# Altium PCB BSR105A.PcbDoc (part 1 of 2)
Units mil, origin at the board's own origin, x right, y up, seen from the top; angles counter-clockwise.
Board outline 4010.03 x 4016.63 mil, 6 copper layers (Top Layer, Mid-Layer 1, Mid-Layer 2, Mid-Layer 3, Mid-Layer 4, Bottom Layer), stack 61.2 mil thick; 166 components, 58 nets, 398 pads, 190 vias.
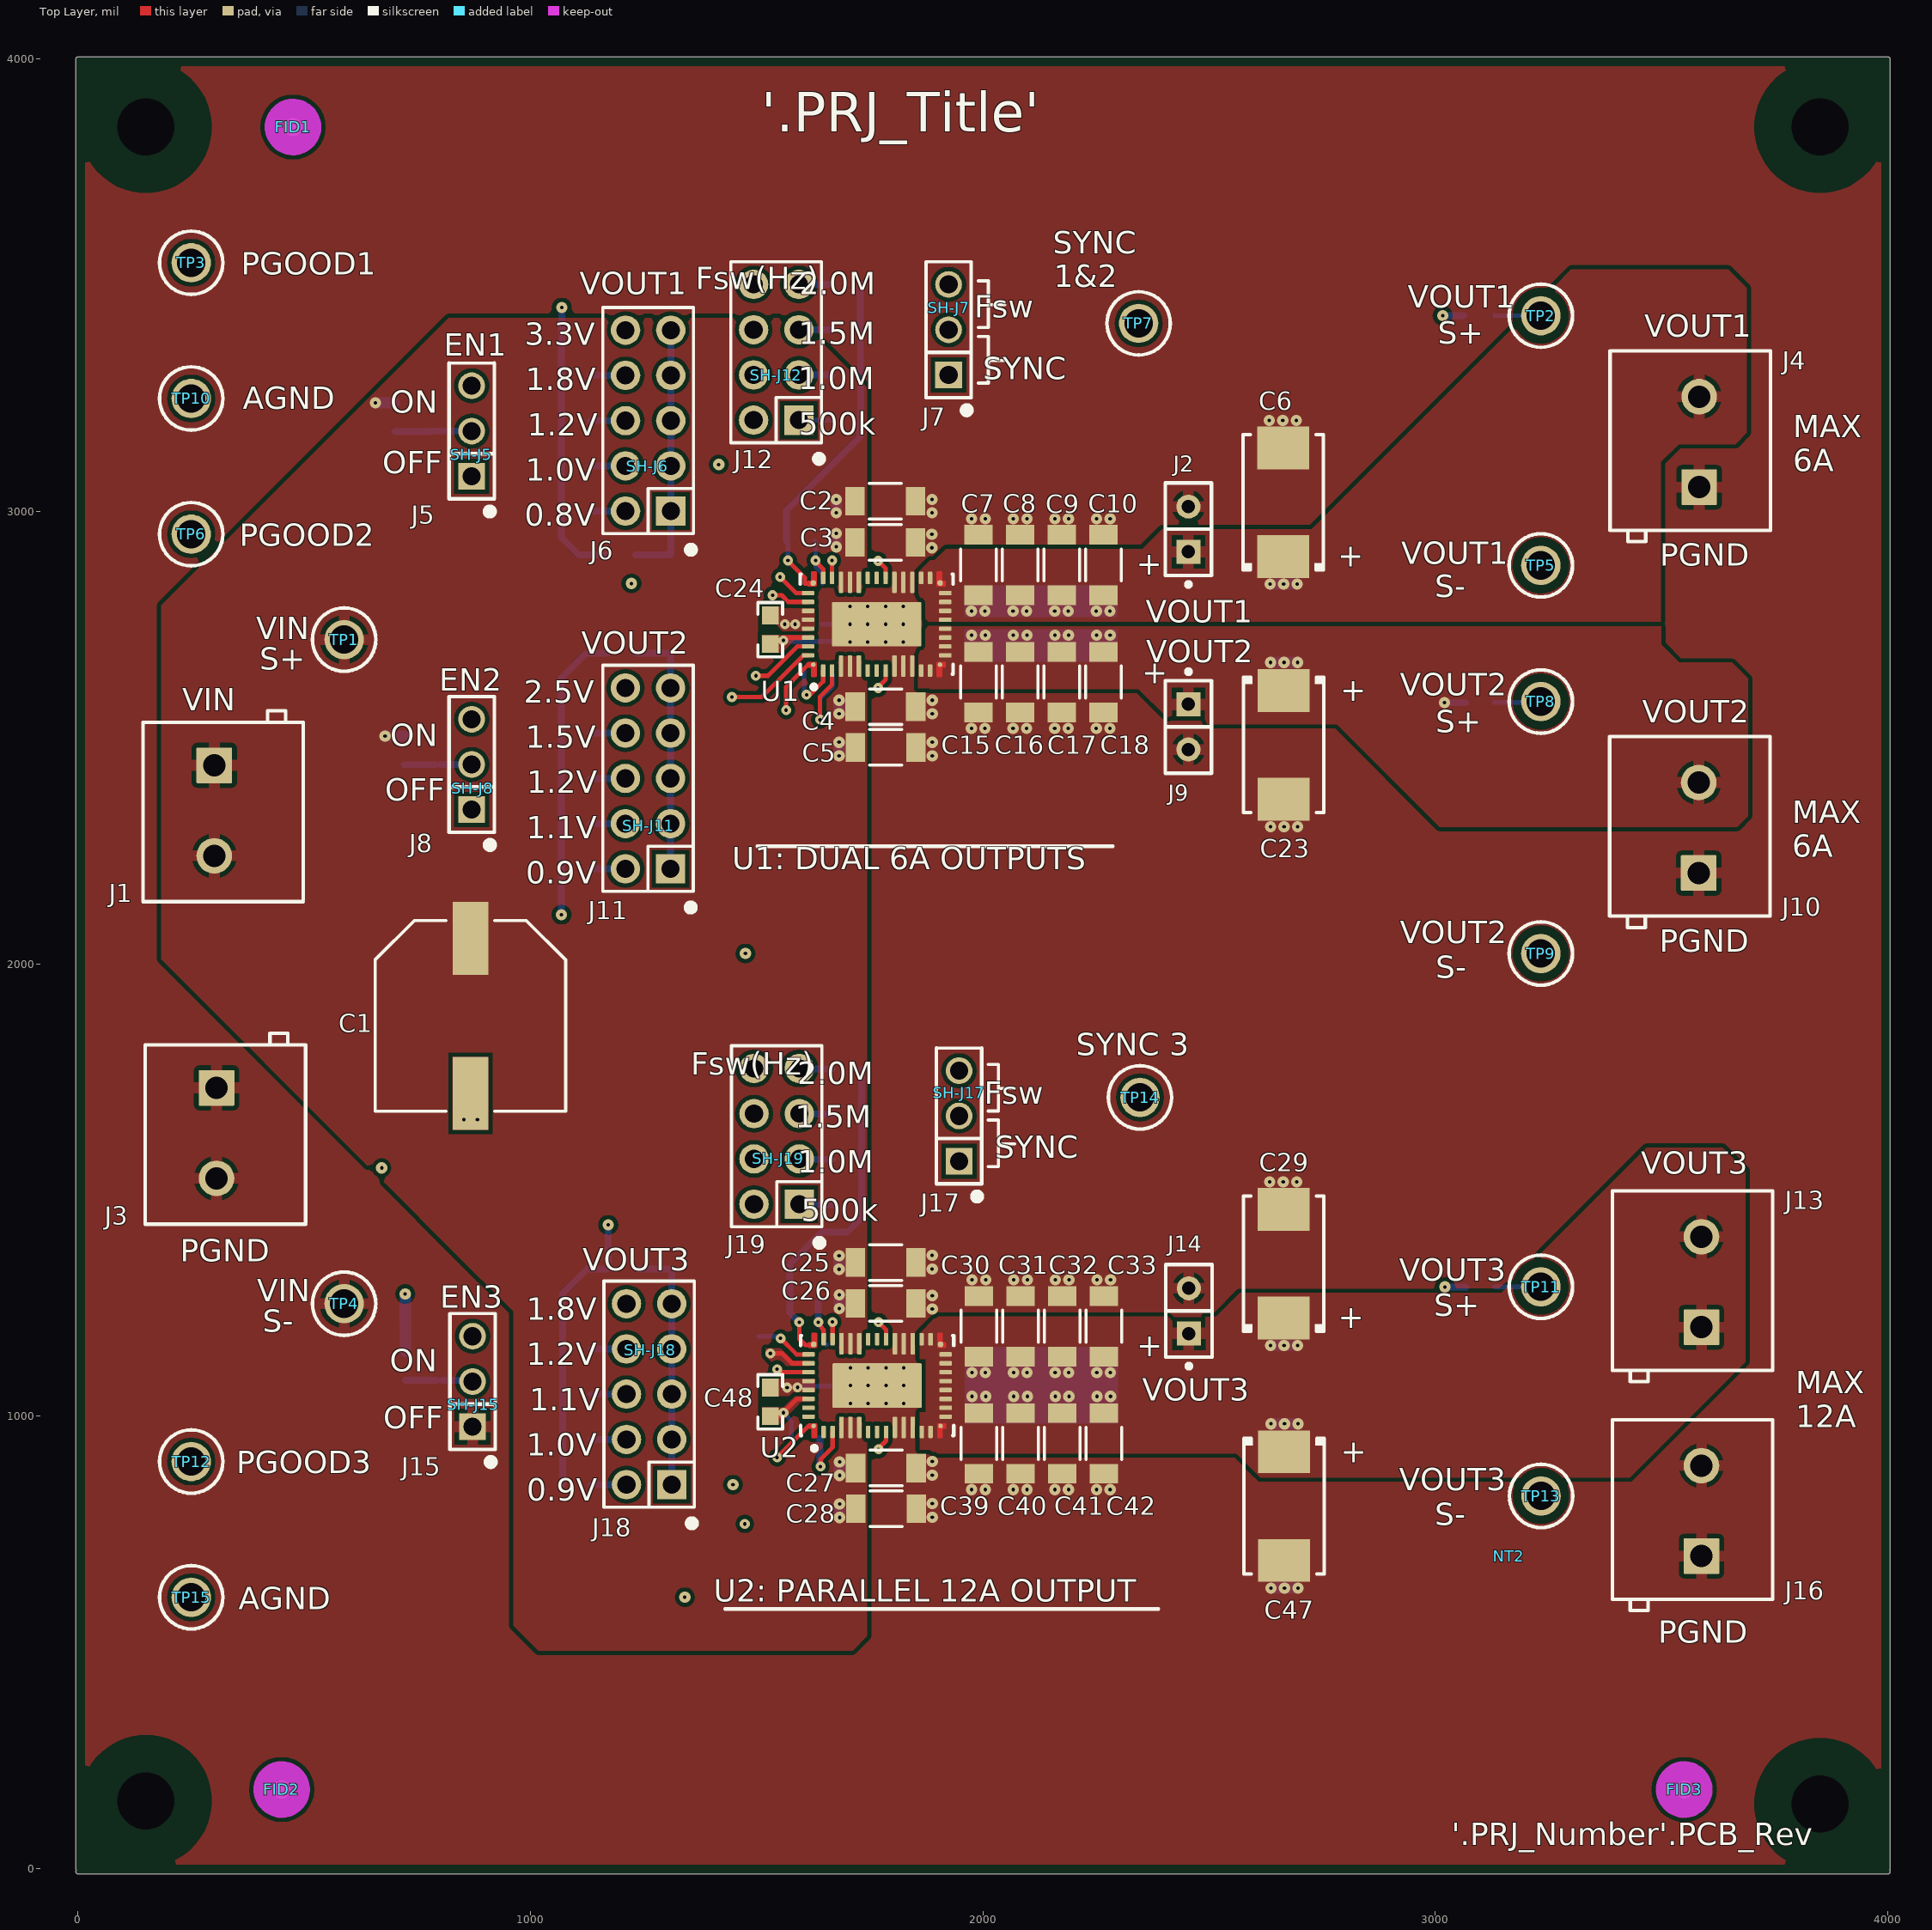
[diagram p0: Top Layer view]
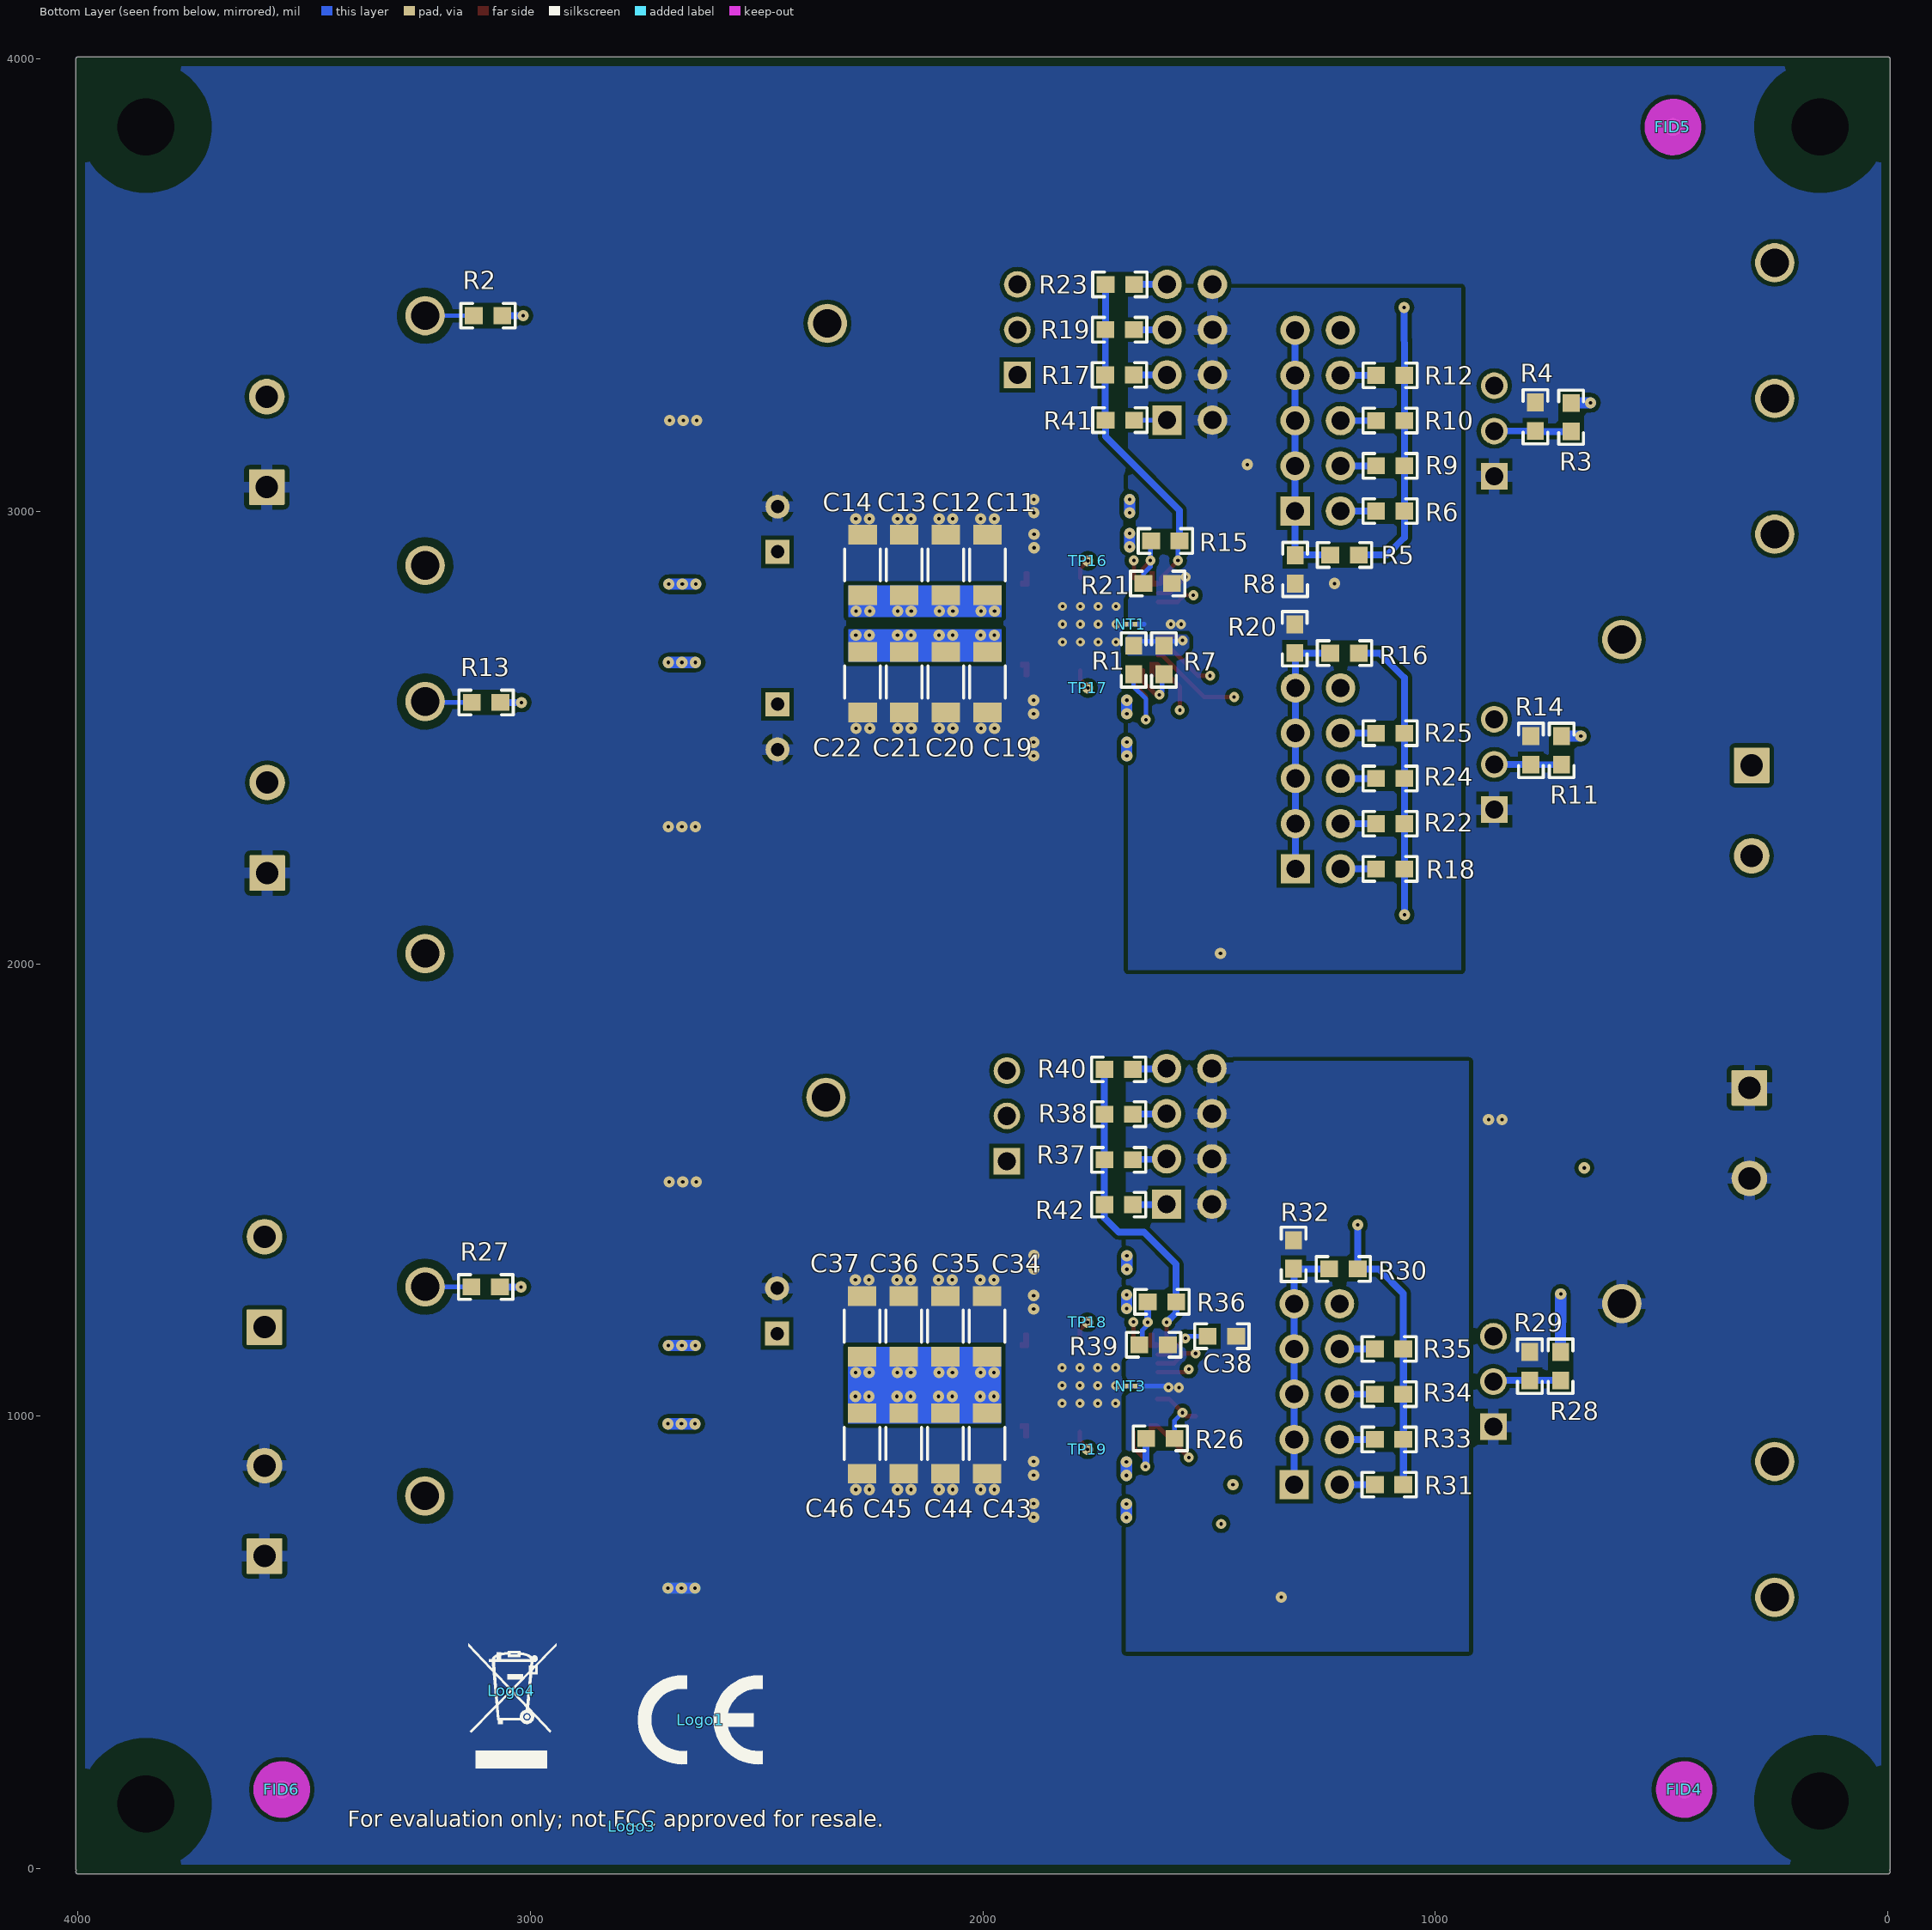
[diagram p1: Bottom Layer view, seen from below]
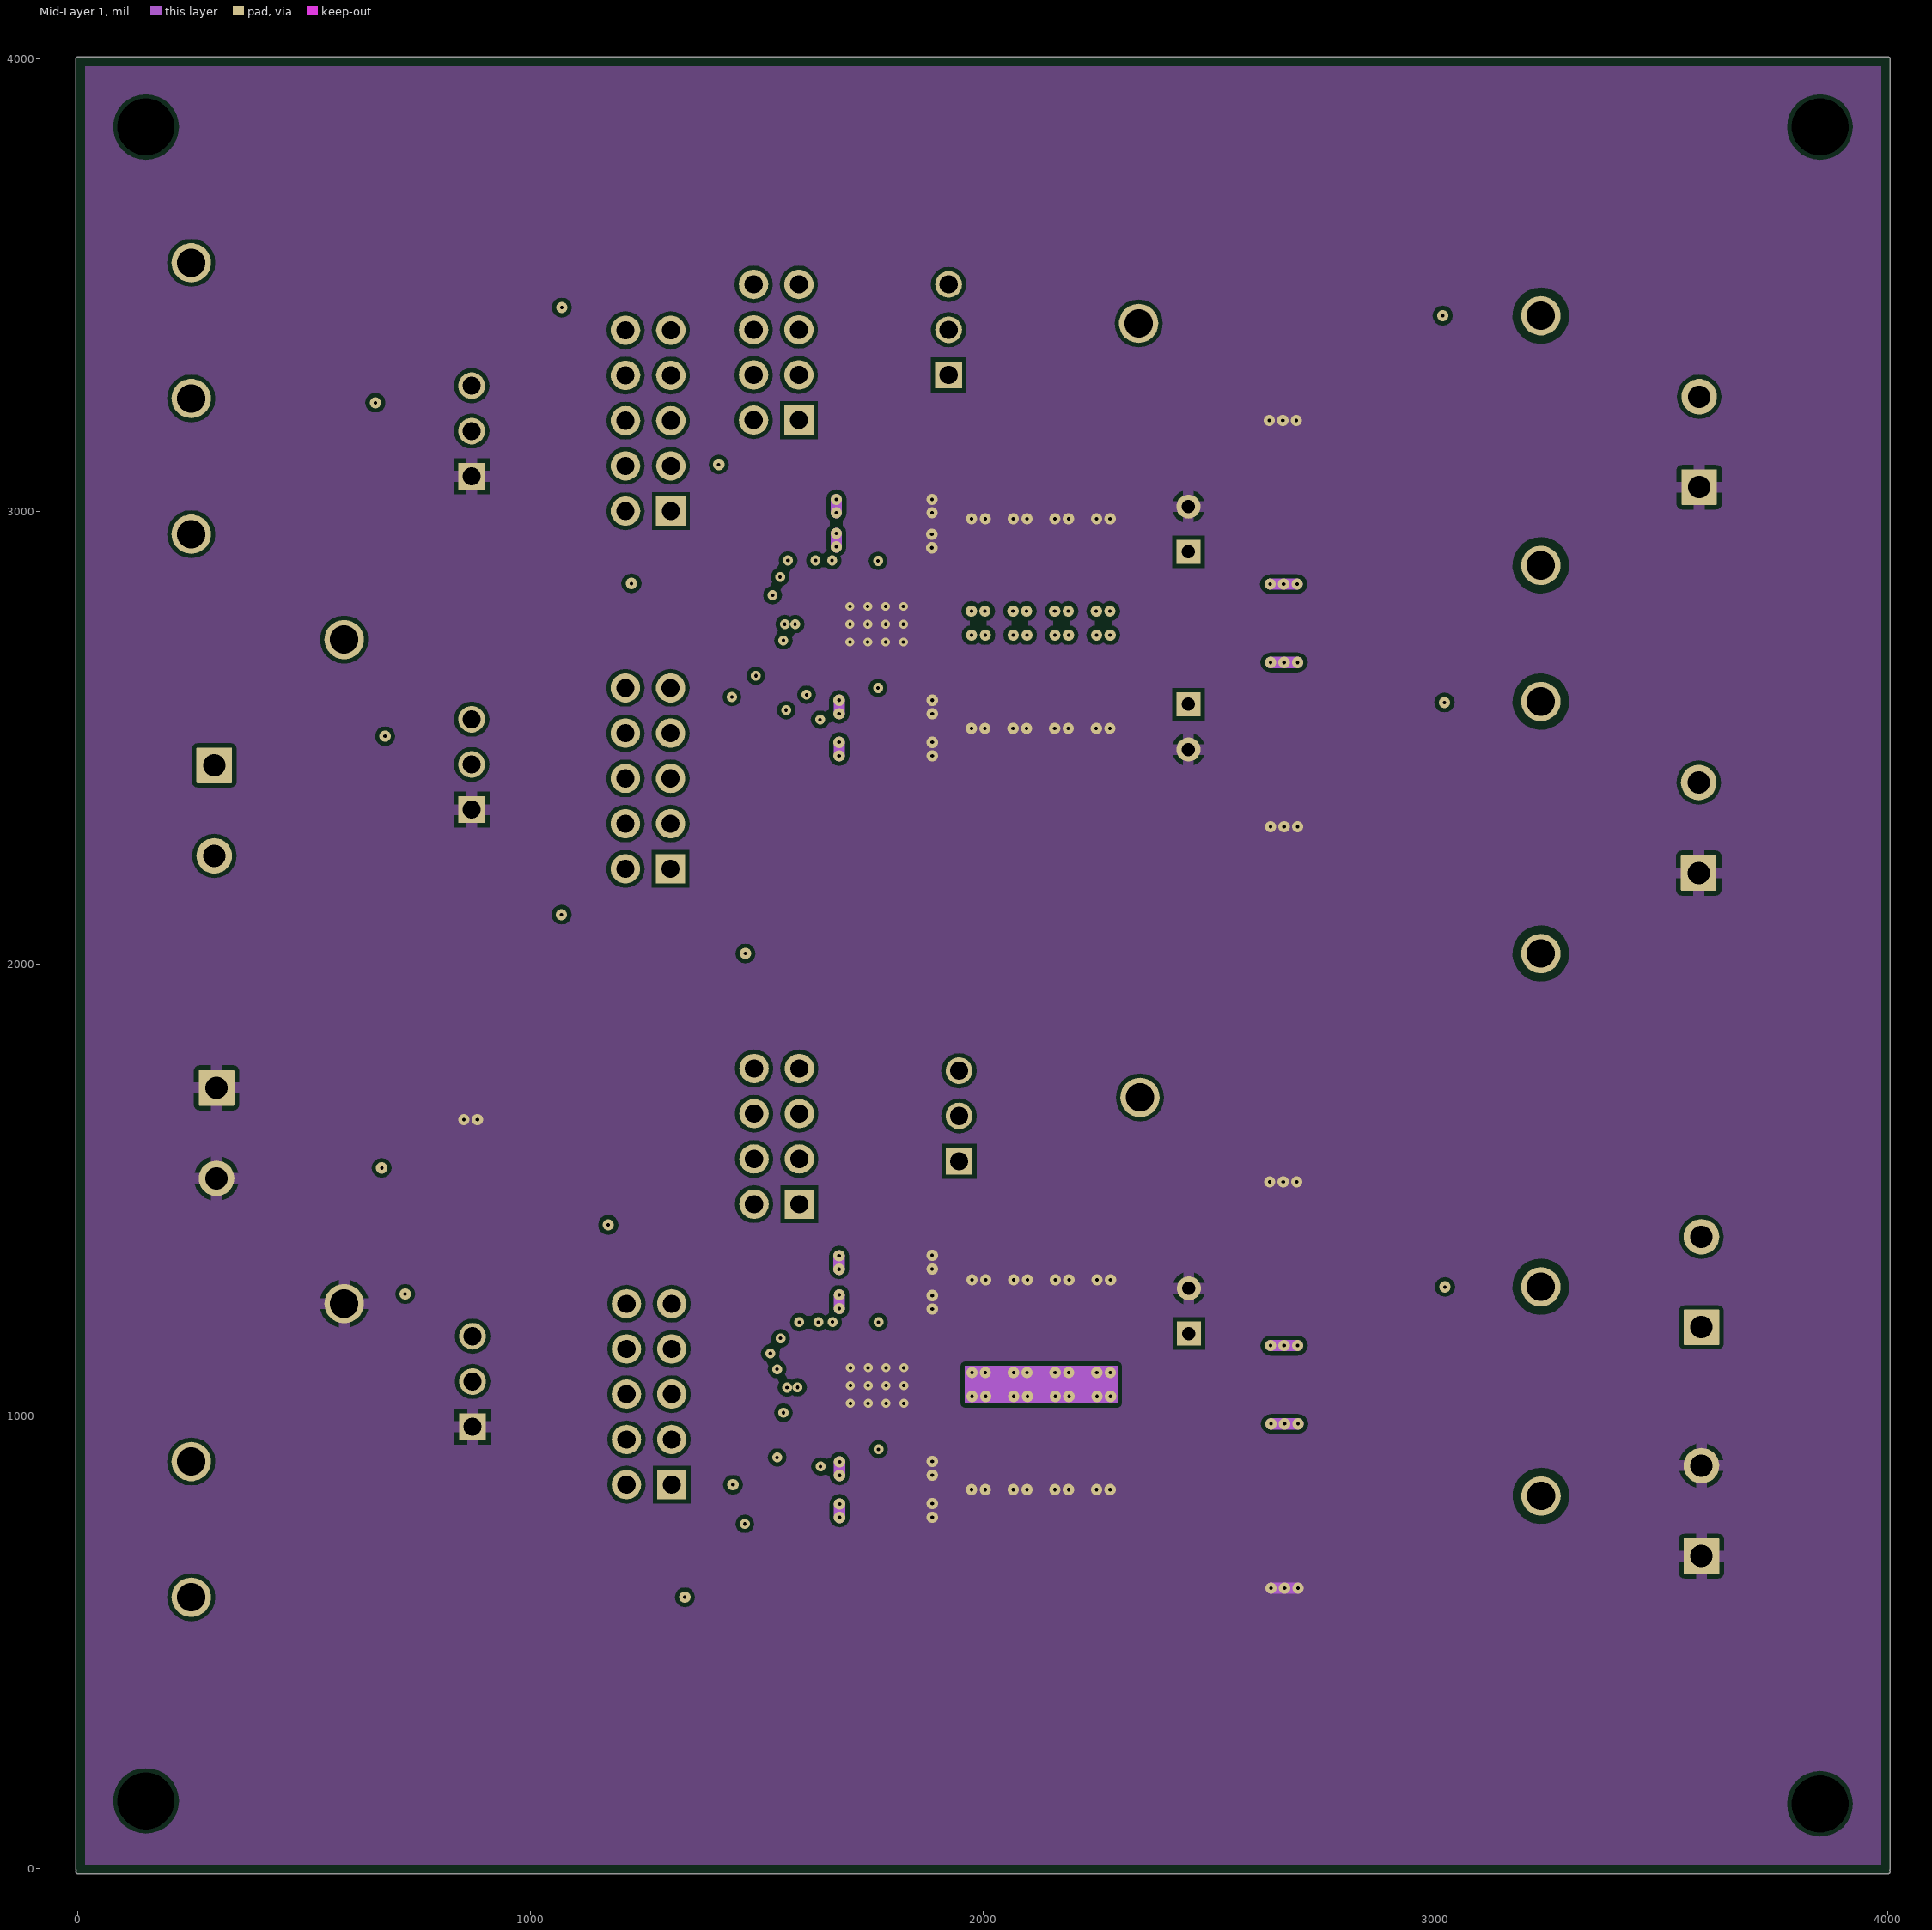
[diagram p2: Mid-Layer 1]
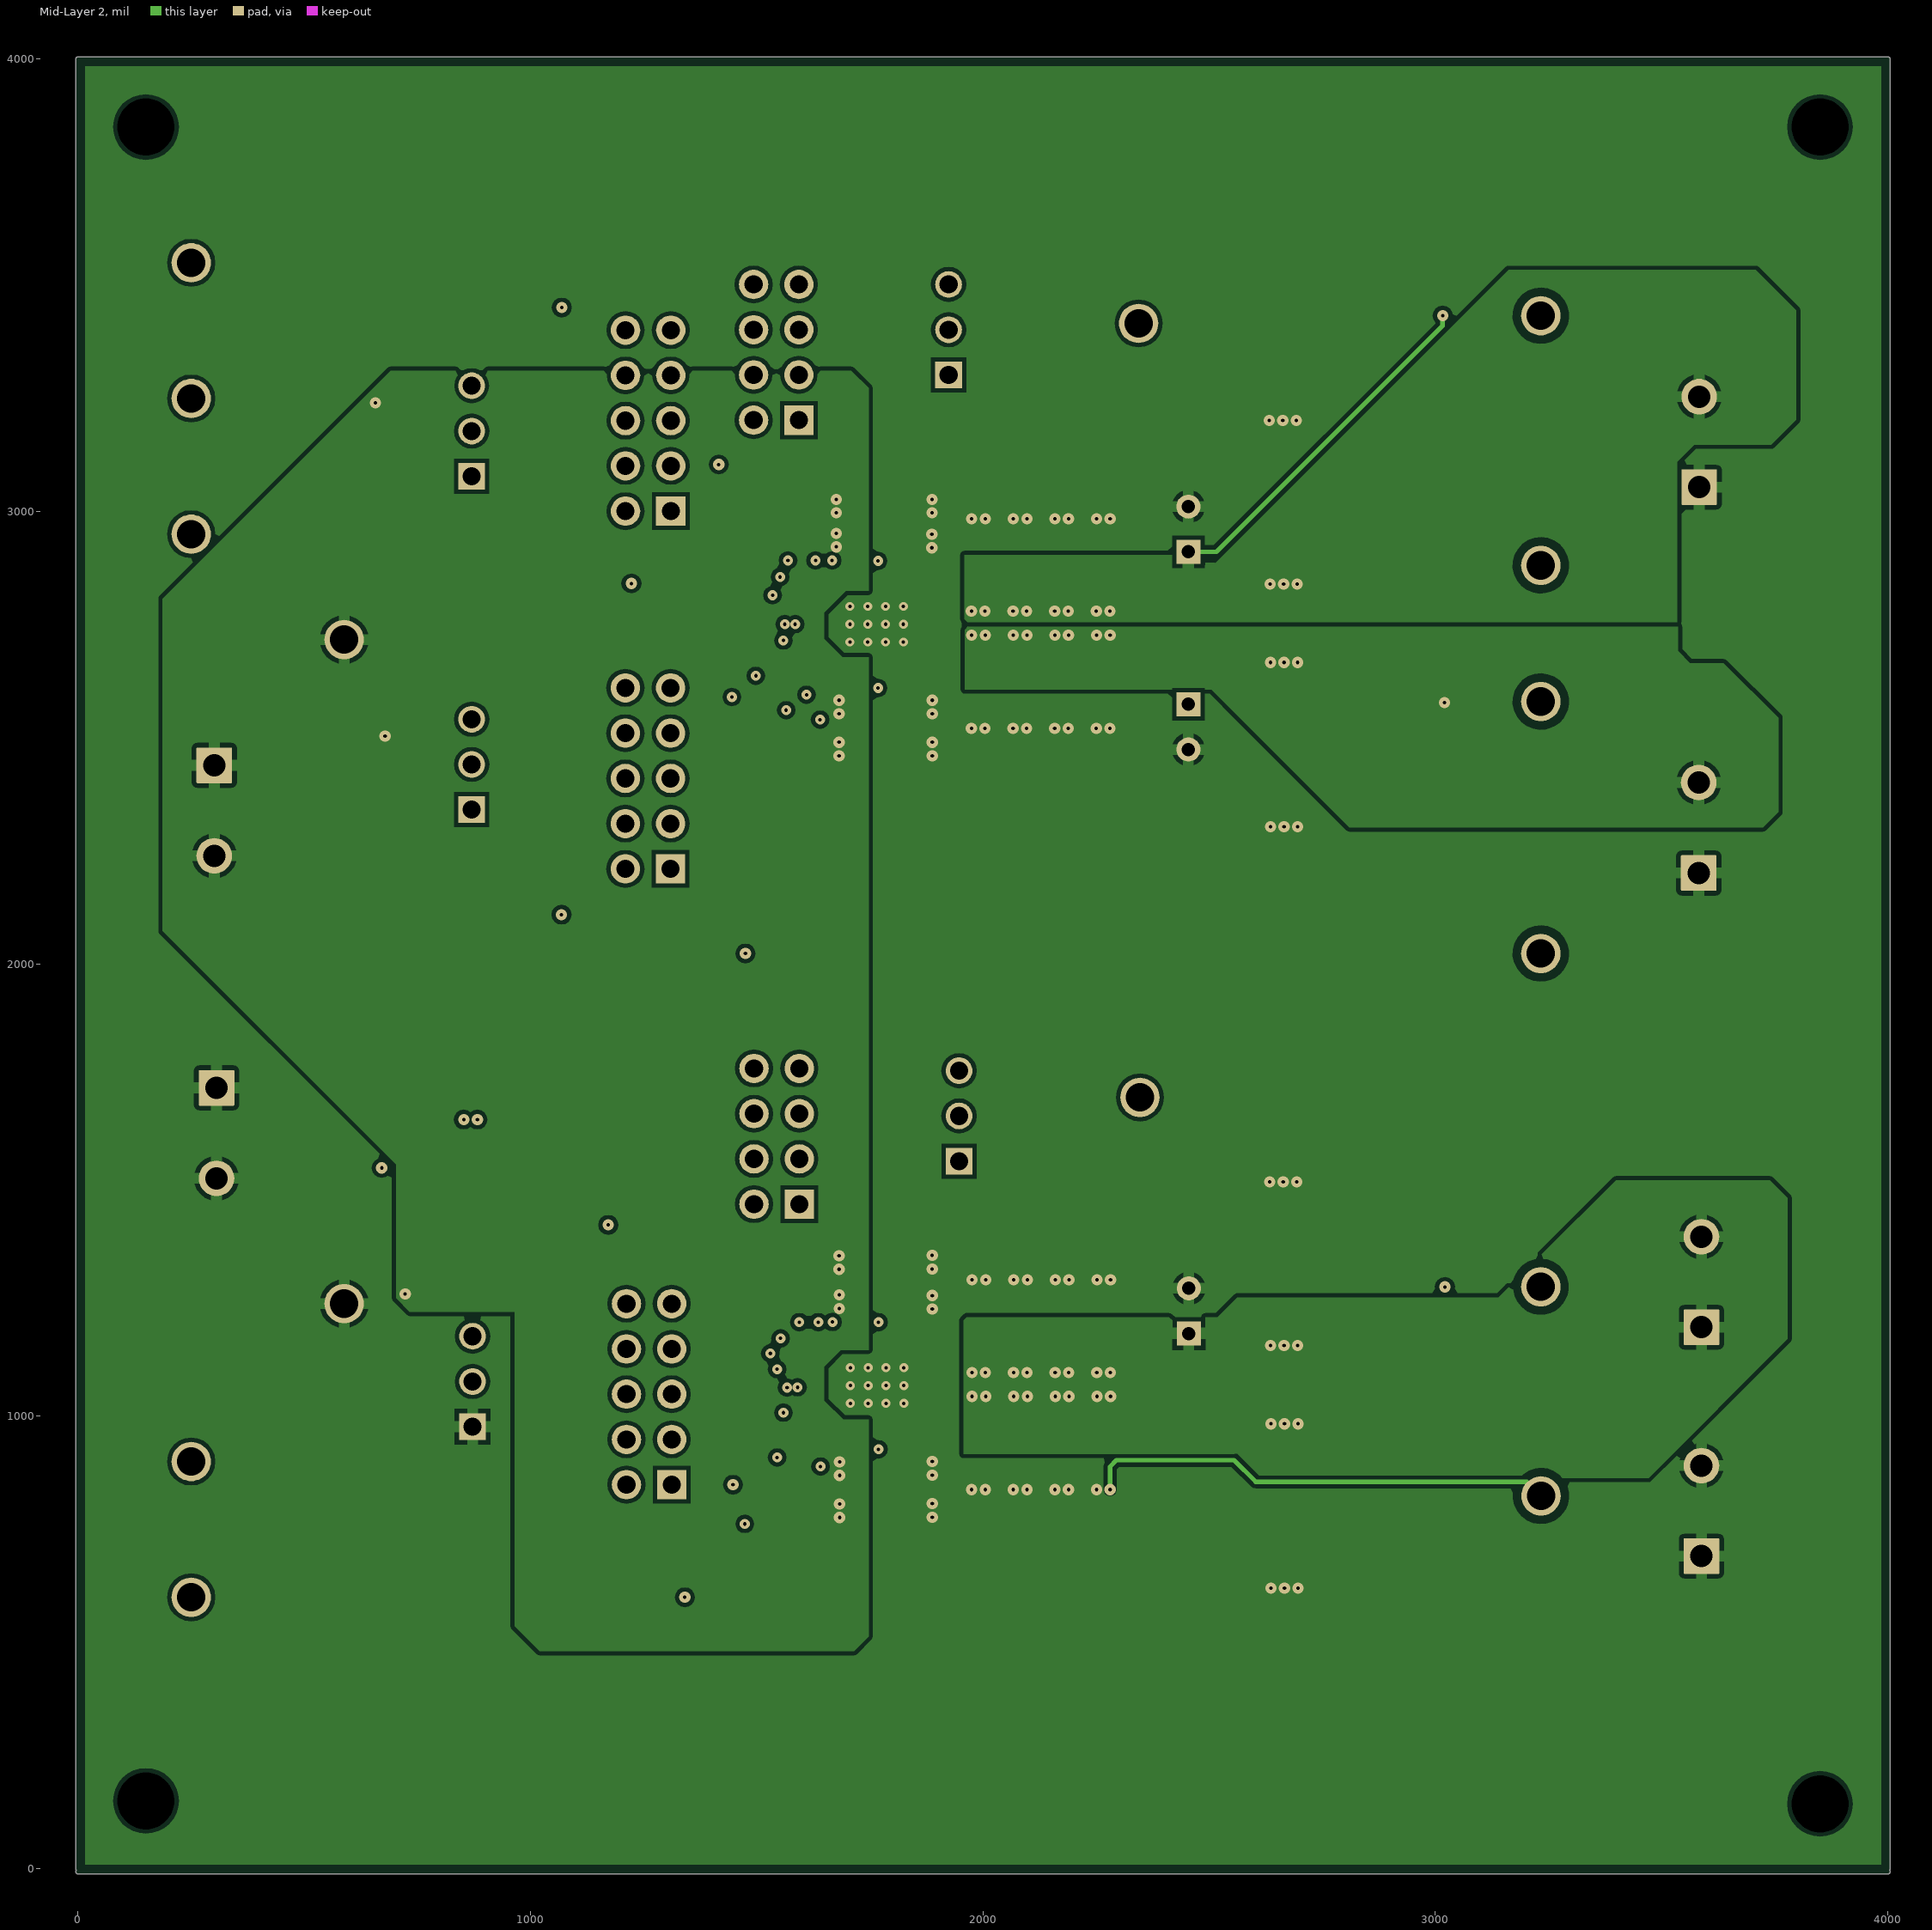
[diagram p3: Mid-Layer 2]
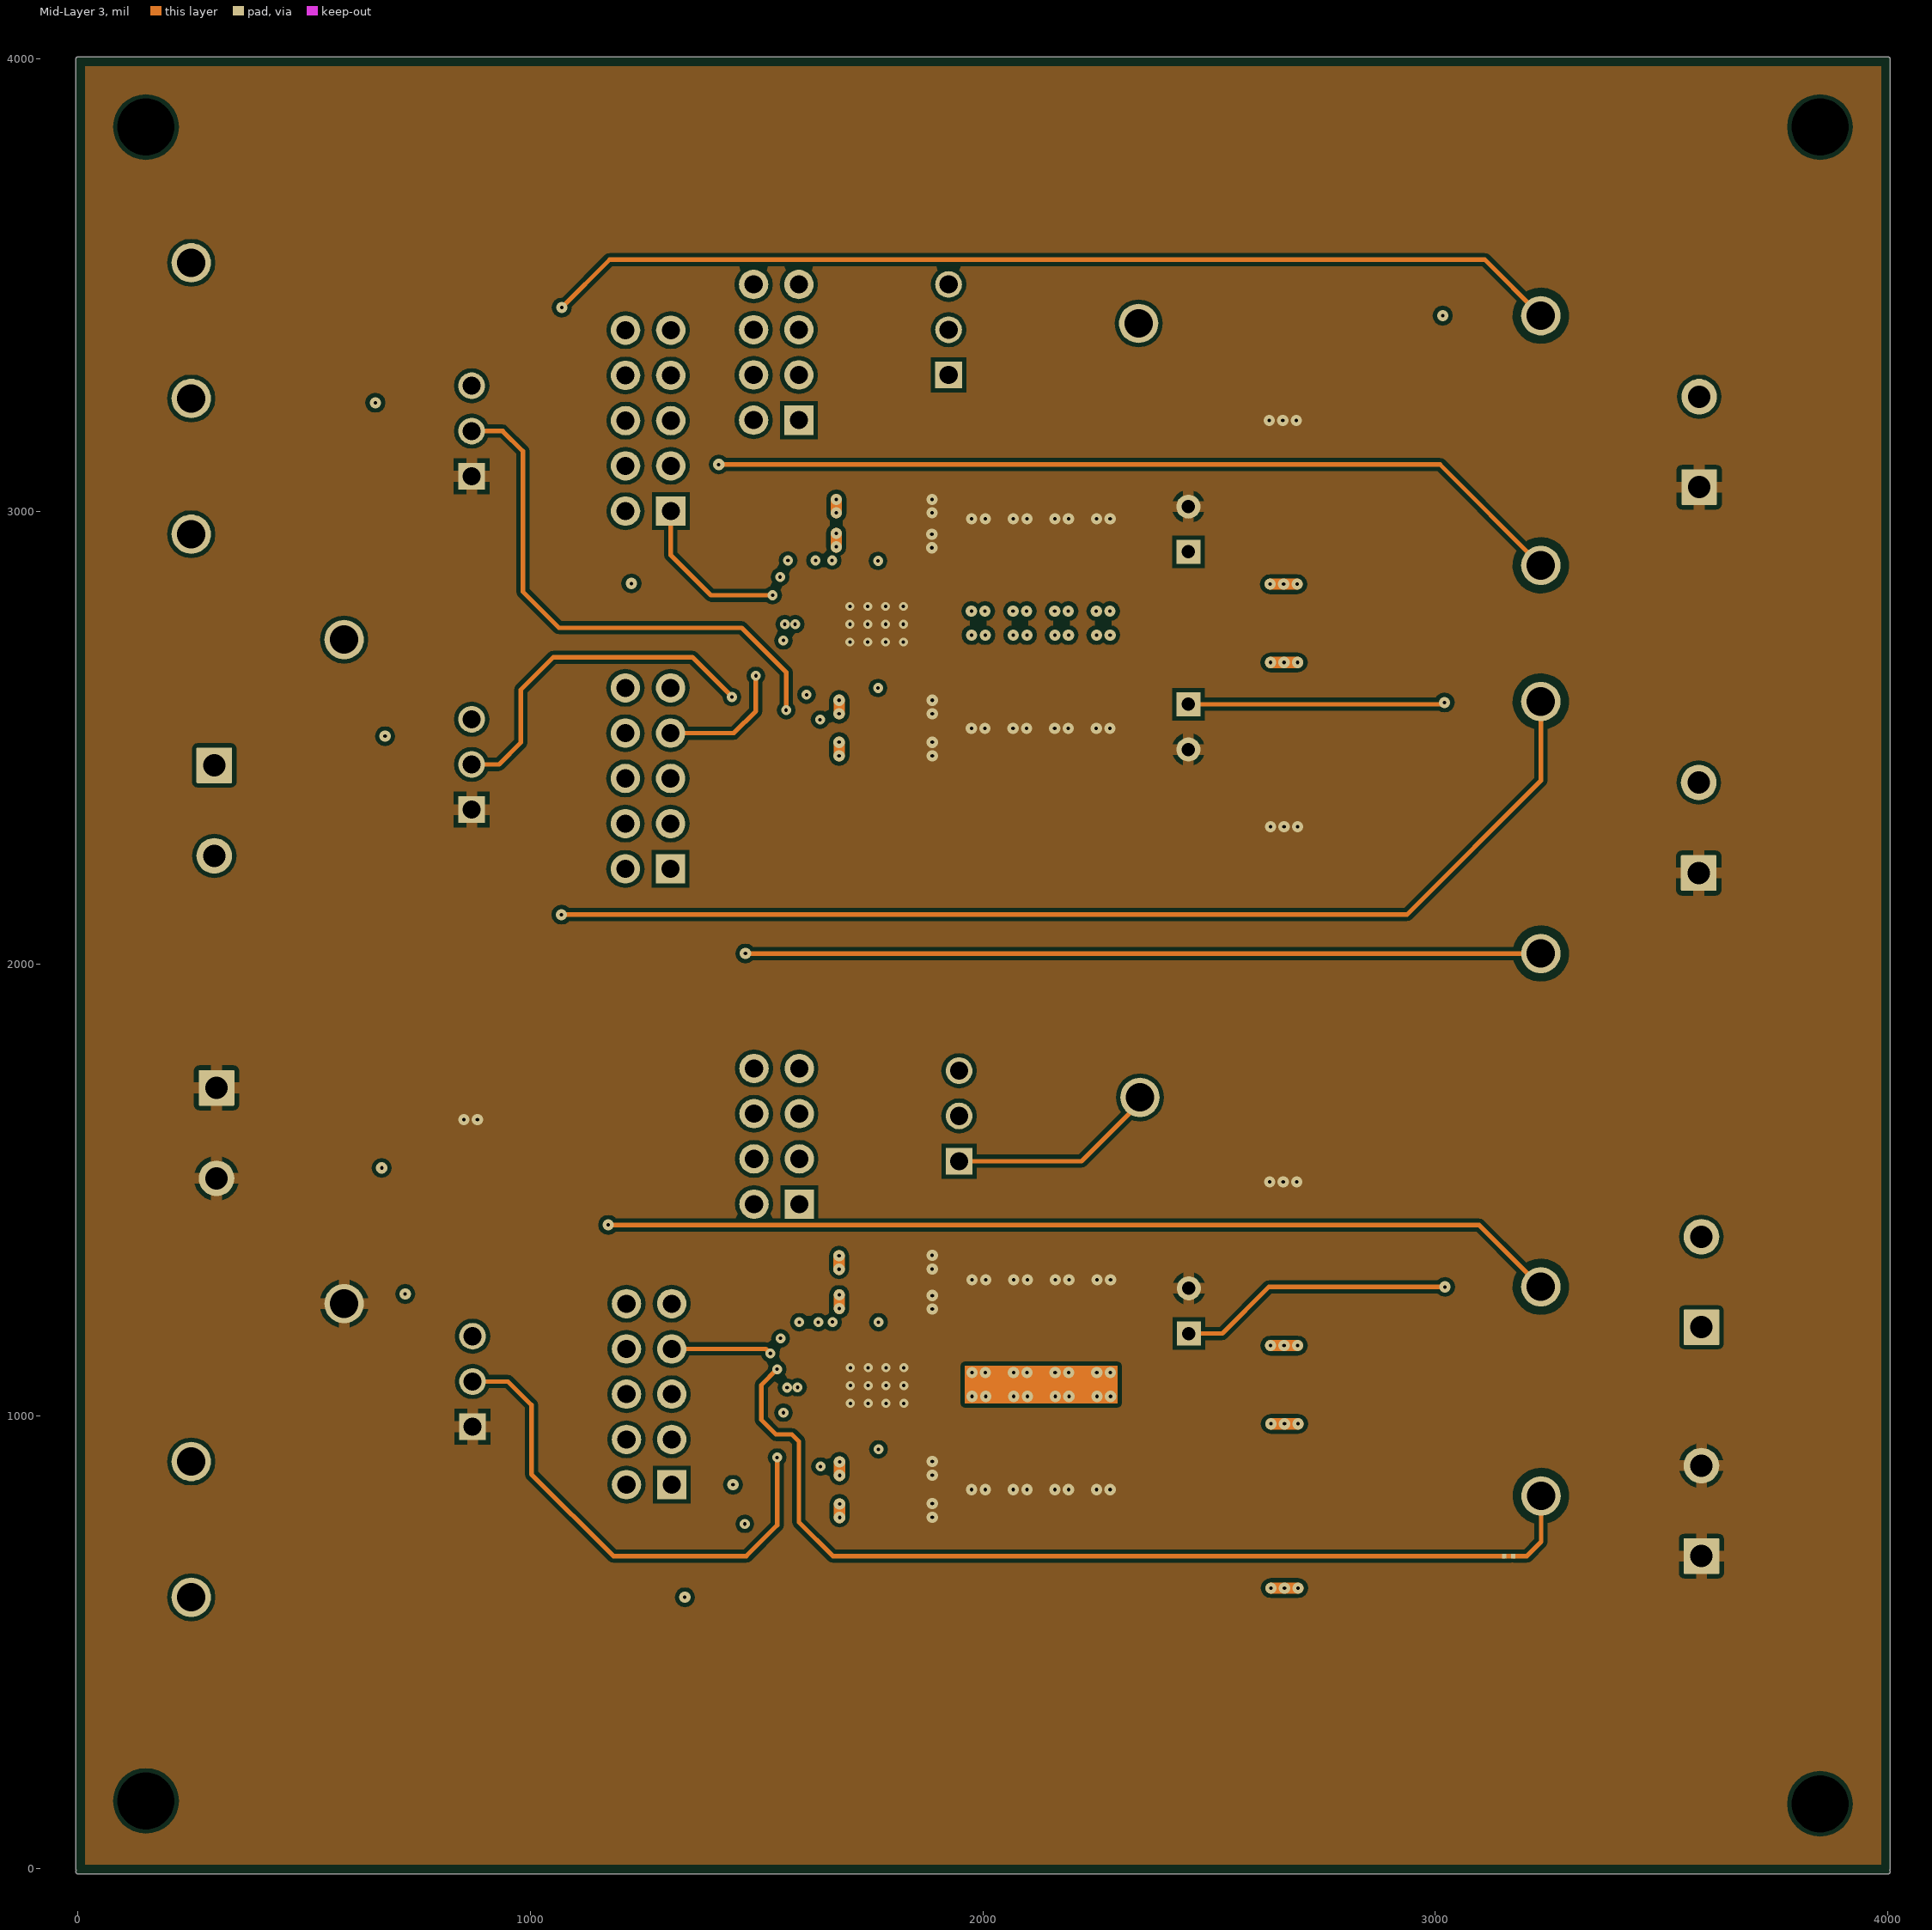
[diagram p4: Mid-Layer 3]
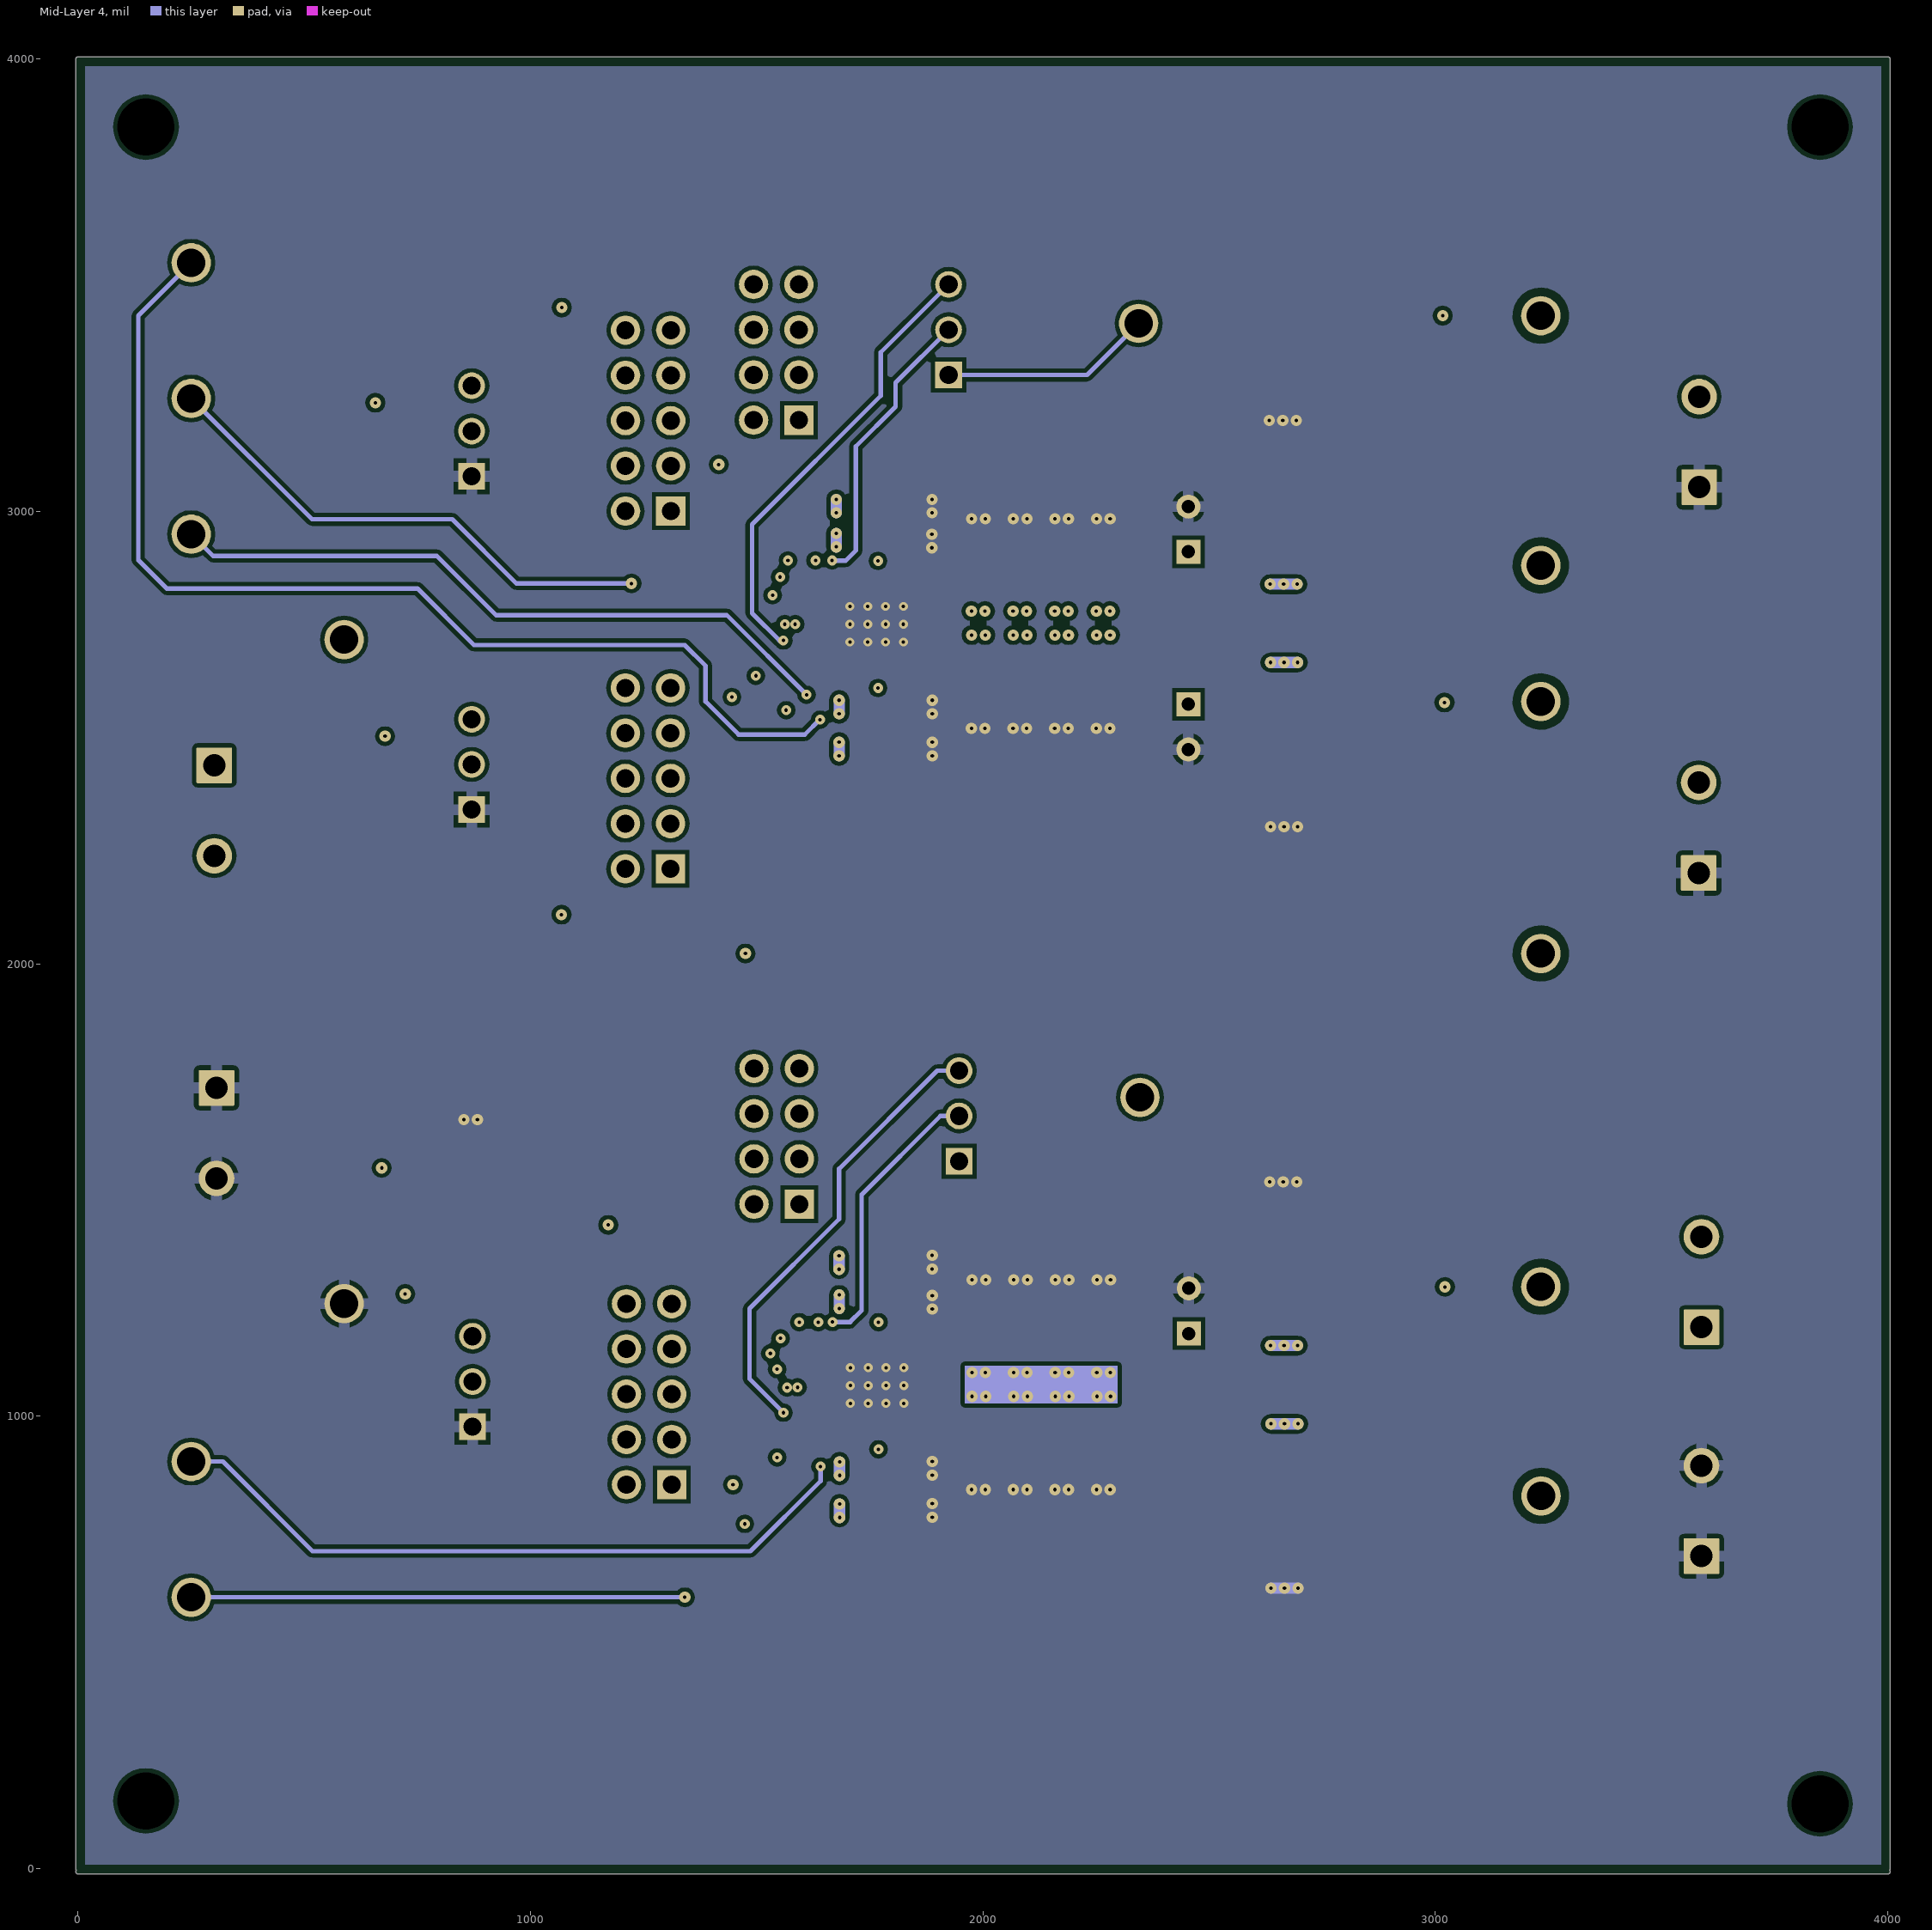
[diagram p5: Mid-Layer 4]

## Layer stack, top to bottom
Top Solder: solder mask 0.4, Solder Resist, Dk 3.5
Top Layer: signal copper 2
Dielectric1: prepreg 5, FR-4, Dk 4.2
Mid-Layer 1: signal copper 2.8
Dielectric2: core 12, FR-4, Dk 4.2
Mid-Layer 2: signal copper 2.8
Dielectric3: prepreg 12, FR-4, Dk 4.2
Mid-Layer 3: signal copper 2.8
Dielectric4: core 12, FR-4, Dk 4.2
Mid-Layer 4: signal copper 2.8
Dielectric5: prepreg 5, FR-4, Dk 4.2
Bottom Layer: signal copper 2
Bottom Solder: solder mask 0.4, Solder Resist, Dk 3.5

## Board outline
0,-11.61 cw(c0,-6.6) -3.78,-3.3 cw(c0,0) -5.01,0 -5.01,4000 cw(c0,4000) 0,4005.02 4000,4005.02 cw(c4000,4000) 4005.02,4000 4005.02,0 cw(c4000,0) 4003.78,-3.3 cw(c4000,-6.6) 4005.02,-6.6 cw(c4000,-6.6) 4000,-11.61

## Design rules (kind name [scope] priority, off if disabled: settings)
AcuteAngle [All] p1: minimum=4.50000000000000E+0001 checktracksonly=FALSE
AssemblyTestPointUsage [All] p1: valid=2
BoardOutlineClearance BoardOutlineClearance_MountingHoles [OnCopper and InComponentClass('Mounting Holes')] p1: gap=40 ignorepadtopadclearanceinfootprint=FALSE
BoardOutlineClearance BoardOutlineClearance_Poly [OnCopper and InPoly] p2: gap=20 ignorepadtopadclearanceinfootprint=FALSE
BoardOutlineClearance [OnCopper and not (InComponentClass('FiducialMark') or (Keepout or IsText) or  InComponentClass('Logo') or InRegion(1000,500,4000,800))] p3: gap=40 ignorepadtopadclearanceinfootprint=FALSE except(20: Poly-OutlineEdge)
Clearance Clearance_U1-U2 [InComponent('U1') and InComponent('U2')] p1: gap=7 ignorepadtopadclearanceinfootprint=FALSE except(0: Arc-Hole Track-Hole SMDPad-Hole THPad-Hole Via-Hole Fill-Hole Poly-Hole Region-Hole Text-Hole; 5.9: SMDPad-SMDPad; 6: Arc-Fill Arc-Poly Arc-Region Track-Fill Track-Poly Track-Region SMDPad-Fill SMDPad-Poly SMDPad-Region Fill-Fill Fill-Poly Fill-Region Poly-Poly Poly-Region Region-Region)
Clearance Clearance_Poly [InPolygon] p2: gap=9 ignorepadtopadclearanceinfootprint=FALSE except(0: Arc-Hole Track-Hole SMDPad-Hole THPad-Hole Via-Hole Fill-Hole Poly-Hole Region-Hole Text-Hole)
Clearance "Clearance_Track and Keepout" [(IsTrack AND OnLayer('Top Layer') AND InNet('VOUT')) vs IsKeepOut] p3: gap=20 ignorepadtopadclearanceinfootprint=FALSE except(0: Arc-Hole Track-Hole SMDPad-Hole THPad-Hole Via-Hole Fill-Hole Poly-Hole Region-Hole Text-Hole)
Clearance "Clearance_Fiducial to Vout" [InComponentClass('FiducialMark') vs (IsTrack AND InNet('VOUT'))] p4: gap=20 ignorepadtopadclearanceinfootprint=FALSE except(0: Arc-Hole Track-Hole SMDPad-Hole THPad-Hole Via-Hole Fill-Hole Poly-Hole Region-Hole Text-Hole)
Clearance Clearance_BoardEdge_Poly [OnCopper and InPoly vs IsKeepOut] p5: gap=25 ignorepadtopadclearanceinfootprint=FALSE except(0: Arc-Hole Track-Hole SMDPad-Hole THPad-Hole Via-Hole Fill-Hole Poly-Hole Region-Hole Text-Hole)
Clearance Clearance_BoardEdge [OnCopper and Not InComponentClass('Logo') and not InComponentClass('FiducialMark') and not InRegion(1000,500,4000,800) and IsKeepOut vs IsKeepOut] p6: gap=22 ignorepadtopadclearanceinfootprint=FALSE except(0: Arc-Hole Track-Hole SMDPad-Hole THPad-Hole Via-Hole Fill-Hole Poly-Hole Region-Hole Text-Hole)
Clearance Clearance_BoardEdge_MountingHoles [OnCopper and InComponentClass('Mounting Holes') vs IsKeepOut] p7: gap=4 ignorepadtopadclearanceinfootprint=FALSE except(0: Arc-Hole Track-Hole SMDPad-Hole THPad-Hole Via-Hole Fill-Hole Poly-Hole Region-Hole Text-Hole)
ComponentClearance ComponentClearance_S11 [InComponent('S11') vs InComponent('V11') or InComponent('Logo3') or InComponent('V12')] p1: gap=0 collisioncheckmode=3 verticalgap=0 showdistances=FALSE
ComponentClearance ComponentClearance_R62 [InComponent('P62') vs InComponent('R63') or InComponent('R64')] p2: gap=0 collisioncheckmode=3 verticalgap=0 showdistances=FALSE
ComponentClearance ComponentClearance_tp13 [InComponent('TP31') vs InComponent('S31')] p3: gap=24 collisioncheckmode=3 verticalgap=0 showdistances=FALSE
ComponentClearance ComponentClearance_P2 [InComponent('P2') vs InComponent('C3') or InComponent('C4')] p4: gap=0 collisioncheckmode=3 verticalgap=0 showdistances=FALSE
ComponentClearance ComponentClearance_Co37 [InComponent('Co37') vs InComponent('V31') or InComponent('V32')] p5: gap=0 collisioncheckmode=3 verticalgap=0 showdistances=FALSE
ComponentClearance ComponentClearance_P12 [InComponent('P12') vs InComponent('R18')] p6: gap=0 collisioncheckmode=3 verticalgap=0 showdistances=FALSE
ComponentClearance ComponentClearance_S1 [InComponent('S1') vs InComponent('TP15')] p7: gap=0 collisioncheckmode=3 verticalgap=0 showdistances=FALSE
ComponentClearance ComponentClearance_R5 [InComponent('R5') vs InComponent('TP13') or InComponent('TP14')] p8: gap=0 collisioncheckmode=3 verticalgap=0 showdistances=FALSE
ComponentClearance ComponentClearance_P61 [InComponent('P61') vs InComponent('R62') or InComponent('J62') or InComponent('R61')] p9: gap=0 collisioncheckmode=3 verticalgap=0 showdistances=FALSE
ComponentClearance ComponentClearance_P1 [InComponent('P1') vs InComponent('R1') or InComponent('R2') or InComponent('R3') or InComponent('R4') or InComponent('R5')] p10: gap=0 collisioncheckmode=3 verticalgap=0 showdistances=FALSE
ComponentClearance "ComponentClearance_P21 to Resistors" [InComponent('P21') vs InComponent('Rs31') or InComponent('Rs32') or InComponent('Rs33') or InComponent('Rs34') or InComponent('Rs35') or InComponent('R37') or InComponent('C34') or InComponent('NT32')] p11: gap=0 collisioncheckmode=3 verticalgap=0 showdistances=FALSE
ComponentClearance "ComponentClearance_P11 to Resistors" [InComponent('P11') vs InComponent('Rs11') or InComponent('Rs12') or InComponent('Rs13') or InComponent('Rs14') or InComponent('Rs15') or InComponent('R17') or InComponent('C14') or InComponent('NT32') or InComponent('NT12')] p12: gap=0 collisioncheckmode=3 verticalgap=0 showdistances=FALSE
ComponentClearance "ComponentClearance_Co17 adn V11" [InComponent('Co17') vs InComponent('V11')] p13: gap=0 collisioncheckmode=3 verticalgap=0 showdistances=FALSE
ComponentClearance "ComponentClearance_P22 and R38" [InComponent('P22') vs InComponent('R38')] p14: gap=0 collisioncheckmode=3 verticalgap=0 showdistances=FALSE
ComponentClearance ComponentClearance_MountingHoles_FiducialMarks [InComponentClass('Mounting Holes') vs InComponentClass('FiducialMark')] p15: gap=50 collisioncheckmode=3 verticalgap=10 showdistances=FALSE
ComponentClearance ComponentClearance_Shunt [InComponentClass('Shunt')] p16: gap=0 collisioncheckmode=3 verticalgap=0 showdistances=FALSE
ComponentClearance ComponentClearance_Logo [InComponentClass('Logo')] p17: gap=25 collisioncheckmode=3 verticalgap=10 showdistances=FALSE
ComponentClearance ComponentClearance_ScrewToNut [(HasFootprint('NY PMS 440 0025 PH')) vs (HasFootprint('Keystone_1902C'))] p18: gap=5 collisioncheckmode=3 verticalgap=10 showdistances=FALSE
ComponentClearance ComponentClearance_MountingHoles [InComponentClass('Mounting Holes')] p19: gap=250 collisioncheckmode=3 verticalgap=100000 showdistances=FALSE
ComponentClearance ComponentClearance_SmallPassives [HasFootprint('0201*') or HasFootprint('0402*') or HasFootprint('0508') or HasFootprint('0603*') or HasFootprint('0612') or HasFootprint('0805*') or HasFootprint('0815*') or HasFootprint('0830*') or HasFootprint('1206*') or HasFootprint('1210*') or HasFootprint('1808*') or HasFootprint('1812*') or HasFootprint('1825*') or HasFootprint('2010*') or HasFootprint('2220*') or HasFootprint('2225*') or HasFootprint('2512*') or HasFootprint('2728*') or HasFootprint('3518*') vs HasFootprint('0201*') or HasFootprint('0402*') or HasFootprint('0508') or HasFootprint('0603*') or HasFootprint('0612') or HasFootprint('0805*') or HasFootprint('0815*') or HasFootprint('0830*') or HasFootprint('1206*') or HasFootprint('1210*') or HasFootprint('1808*') or HasFootprint('1812*') or HasFootprint('1825*') or HasFootprint('2010*') or HasFootprint('2220*') or HasFootprint('2225*') or HasFootprint('2512*') or HasFootprint('2728*') or HasFootprint('3518*')] p20: gap=14.96 collisioncheckmode=3 verticalgap=10 showdistances=FALSE
ComponentClearance ComponentClearance_THtoSMT [IsThruComponent vs IsSMTComponent] p21: gap=10 collisioncheckmode=3 verticalgap=30 showdistances=FALSE
ComponentClearance ComponentClearance_THtoTH [IsThruComponent vs IsThruComponent] p22: gap=30 collisioncheckmode=3 verticalgap=30 showdistances=FALSE
ComponentClearance [All] p23: gap=20 collisioncheckmode=3 verticalgap=10 showdistances=FALSE
DiffPairsRouting [All] p1: maxlimit=100 minlimit=10 mostfreqgap=10 toplayer_minwidth=15 toplayer_maxwidth=15 toplayer_prefwidth=15 midlayer1_minwidth=15 midlayer1_maxwidth=15 midlayer1_prefwidth=15 midlayer2_minwidth=15 midlayer2_maxwidth=15 midlayer2_prefwidth=15 midlayer3_minwidth=15 midlayer3_maxwidth=15 midlayer3_prefwidth=15 midlayer4_minwidth=15 midlayer4_maxwidth=15 midlayer4_prefwidth=15 bottomlayer_minwidth=15 bottomlayer_maxwidth=15 bottomlayer_prefwidth=15 substack1={55F57D56-CF7B-422B-9988-1541B9993FD6} toplayer_{55f57d56-cf7b-422b-9988-1541b9993fd6}_minwidth=15 toplayer_{55f57d56-cf7b-422b-9988-1541b9993fd6}_maxwidth=15 toplayer_{55f57d56-cf7b-422b-9988-1541b9993fd6}_prefwidth=15 midlayer1_{55f57d56-cf7b-422b-9988-1541b9993fd6}_minwidth=15 midlayer1_{55f57d56-cf7b-422b-9988-1541b9993fd6}_maxwidth=15 midlayer1_{55f57d56-cf7b-422b-9988-1541b9993fd6}_prefwidth=15 midlayer2_{55f57d56-cf7b-422b-9988-1541b9993fd6}_minwidth=15 midlayer2_{55f57d56-cf7b-422b-9988-1541b9993fd6}_maxwidth=15 midlayer2_{55f57d56-cf7b-422b-9988-1541b9993fd6}_prefwidth=15 midlayer3_{55f57d56-cf7b-422b-9988-1541b9993fd6}_minwidth=15 midlayer3_{55f57d56-cf7b-422b-9988-1541b9993fd6}_maxwidth=15 midlayer3_{55f57d56-cf7b-422b-9988-1541b9993fd6}_prefwidth=15 midlayer4_{55f57d56-cf7b-422b-9988-1541b9993fd6}_minwidth=15 midlayer4_{55f57d56-cf7b-422b-9988-1541b9993fd6}_maxwidth=15 midlayer4_{55f57d56-cf7b-422b-9988-1541b9993fd6}_prefwidth=15 bottomlayer_{55f57d56-cf7b-422b-9988-1541b9993fd6}_minwidth=15 bottomlayer_{55f57d56-cf7b-422b-9988-1541b9993fd6}_maxwidth=15 bottomlayer_{55f57d56-cf7b-422b-9988-1541b9993fd6}_prefwidth=15 maxuncoupledlength=1000
FabricationTestPointUsage TestPointUsage [All] p1: valid=2 allowmultiple=FALSE
FabricationTestpoint Testpoint [All] p1: side=3 testpointundercomponent=TRUE minsize=40 maxsize=100 preferedsize=60 minholesize=0 maxholesize=40 preferedholesize=32 testpointgrid=1 allowsidetop=TRUE allowsidebottom=TRUE usegrid=TRUE gridtolerance=0.01
FanoutControl Fanout_LCC [IsLCC] p1: bgadir=Out bgaviamode=Centered fanoutstyle=Auto fanoutdirection=Alternating viagrid=1 // Fanout_LCC (Default Rule)
FanoutControl Fanout_BGA [IsBGA] p2: bgadir=Out bgaviamode=Centered fanoutstyle=Auto fanoutdirection=Alternating viagrid=1 // Fanout_BGA (Default Rule)
FanoutControl Fanout_Default [All] p4: bgadir=Out bgaviamode=Centered fanoutstyle=Auto fanoutdirection=Alternating viagrid=1 // Fanout_Default (Default Rule)
FanoutControl Fanout_Small [(CompPinCount < 5)] p5: bgadir=Out bgaviamode=Centered fanoutstyle=Auto fanoutdirection=OutThenIn viagrid=1 // Fanout_Small (Default Rule)
Height [All] p1: minheight=0 maxheight=1200 prefheight=500
HoleSize HoleSize_BGA_Room [All] p1: absolutevalues=TRUE maxlimit=130 minlimit=6 maxpercent=80.000 minpercent=20.000
HoleSize [All] p2: absolutevalues=TRUE maxlimit=251 minlimit=7.87 maxpercent=80.000 minpercent=20.000
MinimumAnnularRing MinimumAnnularRing_ThermalPadVias [IsVia and InAnyComponent] p1: minimumring=5.91
MinimumAnnularRing [All] p2: minimumring=5.9
MinimumSolderMaskSliver MinimumSolderMaskSliver_Logo [InComponentClass('Logo') vs InComponentClass('Logo')] p1: minsoldermaskwidth=0.7
MinimumSolderMaskSliver [All] p2: minsoldermaskwidth=2.95
NetAntennae [IsTrack] p1: netantennaetolerance=0
PlaneConnect [All] p1: planeconnectstyle=Relief reliefexpansion=10 reliefentries=4 reliefconductorwidth=10 reliefairgap=10
PolygonConnect PolygonConnect_Isthrupin [IsThruPin] p1: connectstyle=Relief reliefconductorwidth=25 reliefentries=4 polygonreliefangle="90 Angle" airgapwidth=10
PolygonConnect [All] p2: connectstyle=Direct reliefconductorwidth=10 reliefentries=4 polygonreliefangle="90 Angle" airgapwidth=10
RoutingVias RoutingVias_BGA_Room [All] p1: holewidth=28 width=50 viastyle="Through Hole" minholewidth=6 minwidth=18 maxholewidth=28 maxwidth=50
RoutingVias ThermalPadVias [IsVia and InAnyComponent] p2: holewidth=7.87 width=19.68 viastyle="Through Hole" minholewidth=7.87 minwidth=19.68 maxholewidth=12.99 maxwidth=23.62
RoutingVias [All] p3: holewidth=16 width=34 viastyle="Through Hole" minholewidth=7.87 minwidth=24 maxholewidth=40 maxwidth=65
ShortCircuit ShortCircuit_1 [InNet('AGND') vs InNet('PGND')] p1 off: allowed=TRUE
ShortCircuit [All] p2: allowed=FALSE
SilkToBoardRegionClearance [Not ((IsComment or IsDesignator) And (Hide <> 'False')) and not InRegion(1000,500,4000,800)] p1:
SilkToSilkClearance SilkToSilkClearance_Pb-FreeLogo [(HasFootprint('Pb-Free_Overlay_Medium') OR HasFootprint('Pb-Free_Overlay_Small')) vs (HasFootprint('Pb-Free_Overlay_Medium') OR HasFootprint('Pb-Free_Overlay_Small'))] p1: silktosilkclearance=0
SilkToSilkClearance [All] p2: silktosilkclearance=4
SilkToSolderMaskClearance SilkToComponentPadClearance [IsPad and InAnycomponent] p1: minsilkscreentomaskgap=3 clearancetoexposedcopper=TRUE
SolderMaskExpansion SolderMaskExpansion_Via [Isvia] p1: expansion=0 istentingtop=FALSE
SolderMaskExpansion [All] p2: expansion=1.97 istentingtop=FALSE
Width [All] p1: maxlimit=100 minlimit=8 preferedwidth=10 substack1={55F57D56-CF7B-422B-9988-1541B9993FD6} checkconnectedcopper=TRUE
12 further rules are at their usual default settings.

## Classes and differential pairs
component class AssemblyNote: ZZ1 ZZ2 ZZ3 ZZ4 ZZ5 ZZ6 ZZ7 ZZ8 ZZ9 ZZ10 ZZ11 ZZ12 ZZ13 ZZ14
component class FiducialMark: FID1 FID2 FID3 FID4 FID5 FID6
component class BSR105A_Hardware: FID1 FID2 FID3 FID4 FID5 FID6 Logo1 Logo3 Logo4 SH-J5 SH-J6 SH-J7 SH-J8 SH-J11 SH-J12 SH-J15 SH-J17 SH-J18 SH-J19 ZZ1 ZZ2 ZZ3 ZZ4 ZZ5 ZZ6 ZZ7 ZZ8 ZZ9 ZZ10 ZZ11 ZZ12 ZZ13 ZZ14
component class Header: J5 J6 J7 J8 J11 J12 J15 J17 J18 J19 J53 J54 J61 J62 J63 J64 J65 M23 M31 P54
component class BSR105A_SHT2: C25 C26 C27 C28 C29 C30 C31 C32 C33 C34 C35 C36 C37 C38 C39 C40 C41 C42 C43 C44 C45 C46 C47 C48 Ci13 Co16 Co18 D11 D12 J13 J14 J15 J16 J17 J18 J19 M22 NT2 NT3 P11 P13 R26 R27 R28 R29 R30 R31 R32 R33 R34 R35 R36 R37 R38 R39 R40 R42 R52 Ri0 S3 S12 S22 TP11 TP12 TP13 TP14 TP15 TP18 TP19 TP64 TP67 TP68 U2
component class BSR105A_SHT1: C1 C2 C3 C4 C5 C6 C7 C8 C9 C10 C11 C12 C13 C14 C15 C16 C17 C18 C19 C20 C21 C22 C23 C24 Co37 J1 J2 J3 J4 J5 J6 J7 J8 J9 J10 J11 J12 J25 M31 M42 NT1 R1 R2 R3 R4 R5 R6 R7 R8 R9 R10 R11 R12 R13 R14 R15 R16 R17 R18 R19 R20 R21 R22 R23 R24 R25 R41 TP1 TP2 TP3 TP4 TP5 TP6 TP7 TP8 TP9 TP10 TP16 TP17 U1 V31
component class Shunt: SH-J5 SH-J6 SH-J7 SH-J8 SH-J11 SH-J12 SH-J15 SH-J17 SH-J18 SH-J19

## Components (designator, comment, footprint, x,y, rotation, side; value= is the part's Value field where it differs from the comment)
C1 "EEE-FC1E331P" SM_RADIAL_G 867,1885 r270 top value=330uF
C2 "C3216X5R1E476M160AC" 1206_190 1784,3023 r0 top value=47uF
C3 "C3216X5R1E476M160AC" 1206_190 1784,2932 r0 top value=47uF
C4 "C3216X5R1E476M160AC" 1206_190 1784.65,2568.64 r0 top value=47uF
C5 "C3216X5R1E476M160AC" 1206_190 1784.82,2478.55 r0 top value=47uF
C6 "T520Y337M010ATE035" 7343-40 2663.5,3020.41 r90 top value=330uF
C7 "GRM31CR60J107ME39L" 1206_180 1990,2882 r90 top value=100uF
C8 "GRM31CR60J107ME39L" 1206_180 2082,2882 r90 top value=100uF
C9 "GRM31CR60J107ME39L" 1206_180 2174,2882 r90 top value=100uF
C10 "GRM31CR60J107ME39L" 1206_180 2266,2882 r90 top value=100uF
C11 "GRM31CR60J107ME39L" 1206_180 1990,2882 r90 bottom value=100uF
C12 "GRM31CR60J107ME39L" 1206_180 2082,2882 r90 bottom value=100uF
C13 "GRM31CR60J107ME39L" 1206_180 2174,2882 r90 bottom value=100uF
C14 "GRM31CR60J107ME39L" 1206_180 2266,2882 r90 bottom value=100uF
C15 "GRM31CR60J107ME39L" 1206_180 1990,2623 r270 top value=100uF
C16 "GRM31CR60J107ME39L" 1206_180 2082,2623 r270 top value=100uF
C17 "GRM31CR60J107ME39L" 1206_180 2174,2623 r270 top value=100uF
C18 "GRM31CR60J107ME39L" 1206_180 2266,2623 r270 top value=100uF
C19 "GRM31CR60J107ME39L" 1206_180 1990,2623 r270 bottom value=100uF
C20 "GRM31CR60J107ME39L" 1206_180 2082,2623 r270 bottom value=100uF
C21 "GRM31CR60J107ME39L" 1206_180 2174,2623 r270 bottom value=100uF
C22 "GRM31CR60J107ME39L" 1206_180 2266,2623 r270 bottom value=100uF
C23 "T520Y337M010ATE035" 7343-40 2664.5,2484.41 r270 top value=330uF
C24 "C1608X6S1C225K080AC" 0603 1530,2739 r90 top value=2.2uF
C25 "C3216X5R1E476M160AC" 1206_190 1784.82,1340.08 r0 top value=47uF
C26 "C3216X5R1E476M160AC" 1206_190 1785,1249.66 r0 top value=47uF
C27 "C3216X5R1E476M160AC" 1206_190 1785.65,885.64 r0 top value=47uF
C28 "C3216X5R1E476M160AC" 1206_190 1785.82,795.55 r0 top value=47uF
C29 "T520Y337M010ATE035" 7343-40 2664.5,1337.41 r90 top value=330uF
C30 "GRM31CR60J107ME39L" 1206_180 1991,1199 r90 top value=100uF
C31 "GRM31CR60J107ME39L" 1206_180 2083,1199 r90 top value=100uF
C32 "GRM31CR60J107ME39L" 1206_180 2175,1199 r90 top value=100uF
C33 "GRM31CR60J107ME39L" 1206_180 2267,1199 r90 top value=100uF
C34 "GRM31CR60J107ME39L" 1206_180 1991,1199 r90 bottom value=100uF
C35 "GRM31CR60J107ME39L" 1206_180 2083,1199 r90 bottom value=100uF
C36 "GRM31CR60J107ME39L" 1206_180 2175,1199 r90 bottom value=100uF
C37 "GRM31CR60J107ME39L" 1206_180 2267,1199 r90 bottom value=100uF
C38 "C1608X7R1H473K080AA" 0603 1472,1177 r180 bottom value=0.047uF
C39 "GRM31CR60J107ME39L" 1206_180 1991,940 r270 top value=100uF
C40 "GRM31CR60J107ME39L" 1206_180 2083,940 r270 top value=100uF
C41 "GRM31CR60J107ME39L" 1206_180 2175,940 r270 top value=100uF
C42 "GRM31CR60J107ME39L" 1206_180 2267,940 r270 top value=100uF
C43 "GRM31CR60J107ME39L" 1206_180 1991,940 r270 bottom value=100uF
C44 "GRM31CR60J107ME39L" 1206_180 2083,940 r270 bottom value=100uF
C45 "GRM31CR60J107ME39L" 1206_180 2175,940 r270 bottom value=100uF
C46 "GRM31CR60J107ME39L" 1206_180 2267,940 r270 bottom value=100uF
C47 "T520Y337M010ATE035" 7343-40 2665.5,801.41 r270 top value=330uF
C48 "C1608X6S1C225K080AC" 0603 1530,1032 r90 top value=2.2uF
FID1 "Fiducial" Fiducial10-30 475,3850 r0 top
FID2 "Fiducial" Fiducial10-30 450,175 r0 top
FID3 "Fiducial" Fiducial10-30 3550,175 r0 top
FID4 "Fiducial" Fiducial10-30 450,175 r180 bottom
FID5 "Fiducial" Fiducial10-30 475,3850 r180 bottom
FID6 "Fiducial" Fiducial10-30 3550,175 r180 bottom
J1 "ED120/2DS" On-Shore_ED120_2DS 301,2339 r270 top
J2 "310-43-102-41-001000" Mill-max_310-43-102-41-001000 2454,2961 r90 top
J3 "ED120/2DS" On-Shore_ED120_2DS 306,1626 r270 top
J4 "ED120/2DS" On-Shore_ED120_2DS 3583,3154 r90 top
J5 "PEC03SAAN" CONN_PEC03SAAN 870,3178 r90 top
J6 "PEC05DAAN" CONN_PEC05DAAN 1260,3201 r90 top
J7 "PEC03SAAN" CONN_PEC03SAAN 1924,3402 r90 top
J8 "PEC03SAAN" CONN_PEC03SAAN 870,2441 r90 top
J9 "310-43-102-41-001000" Mill-max_310-43-102-41-001000 2454,2524 r270 top
J10 "ED120/2DS" On-Shore_ED120_2DS 3582,2301 r90 top
J11 "PEC05DAAN" CONN_PEC05DAAN 1259.59,2410.17 r90 top
J12 "PEC04DAAN" CONN_PEC04DAAN 1543,3352 r90 top
J13 "ED120/2DS" On-Shore_ED120_2DS 3588,1297 r90 top
J14 "310-43-102-41-001000" Mill-max_310-43-102-41-001000 2455,1233 r90 top
J15 "PEC03SAAN" CONN_PEC03SAAN 872,1077 r90 top
J16 "ED120/2DS" On-Shore_ED120_2DS 3588,791 r90 top
J17 "PEC03SAAN" CONN_PEC03SAAN 1947,1664 r90 top
J18 "PEC05DAAN" CONN_PEC05DAAN 1262,1049 r90 top
J19 "PEC04DAAN" CONN_PEC04DAAN 1544,1619 r90 top
Logo1 "CE Mark" CE_Mark_5mm 2625,329 r180 bottom
Logo3 "FCC disclaimer" FCC_disclaimer 2777,94 r180 bottom
Logo4 "WEEE logo" WEEE_Minimum 3042,394 r180 bottom
NT1 "Net-Tie" Net-Tie_10mil#1 1674,2751 r0 bottom net-tie
NT2 "Net-Tie" Net-Tie_10mil#2 3162,691 r0 top net-tie
NT3 "Net-Tie" Net-Tie_10mil#1 1674,1067 r0 bottom net-tie
R1 "CRCW060310K0FKEA" 0603 1667,2672 r90 bottom value=10.0k
R2 "CRCW06030000Z0EA" 0603 3094,3433 r180 bottom value=0
R3 "CRCW0603100KFKEA" 0603 700,3208.59 r90 bottom value=100k
R4 "CRCW060334K8FKEA" 0603 779,3209.59 r270 bottom value=34.8k
R5 "CRCW060356K2FKEA" 0603 1201,2904 r180 bottom value=56.2k
R6 "CRCW06036K81FKEA" 0603 1100,3001 r180 bottom value=6.81k
R7 "CRCW060310K0FKEA" 0603 1600,2672 r90 bottom value=10.0k
R8 "CRCW060310K0FKEA" 0603 1310,2872 r90 bottom value=10.0k
R9 "CRCW060312K1FKEA" 0603 1100,3101 r180 bottom value=12.1k
R10 "CRCW060318K7FKEA" 0603 1100,3201 r180 bottom value=18.7k
R11 "CRCW0603100KFKEA" 0603 721,2472 r90 bottom value=100k
R12 "CRCW060348K7FKEA" 0603 1100,3301 r180 bottom value=48.7k
R13 "CRCW06030000Z0EA" 0603 3098,2578 r180 bottom value=0
R14 "CRCW060334K8FKEA" 0603 789,2472 r270 bottom value=34.8k
R15 "CRCW060310K0FKEA" 0603 1597,2935 r0 bottom value=10.0k
R16 "CRCW060340K2FKEA" 0603 1201,2687 r180 bottom value=40.2k
R17 "CRCW060317K4FKEA" 0603 1698.5,3302 r0 bottom value=17.4k
R18 "CRCW060310K0FKEA" 0603 1100,2210 r180 bottom value=10.0k
R19 "CRCW060328K7FKEA" 0603 1698,3402 r0 bottom value=28.7k
R20 "CRCW060310K0FKEA" 0603 1311,2719 r270 bottom value=10.0k
R21 "CRCW060315K4FKEA" 0603 1614,2841 r0 bottom value=15.4k
R22 "CRCW060317K4FKEA" 0603 1100,2310 r180 bottom value=17.4k
R23 "CRCW060353K6FKEA" 0603 1697.5,3502 r0 bottom value=53.6k
R24 "CRCW060321K5FKEA" 0603 1100,2410 r180 bottom value=21.5k
R25 "CRCW060340K2FKEA" 0603 1100,2510 r180 bottom value=40.2k
R26 "CRCW060310K0FKEA" 0603 1608,951 r180 bottom value=10.0k
R27 "CRCW06030000Z0EA" 0603 3099,1286 r180 bottom value=0
R28 "CRCW0603100KFKEA" 0603 723.41,1110.83 r90 bottom value=100k
R29 "CRCW060334K8FKEA" 0603 791.41,1110.83 r270 bottom value=34.8k
R30 "CRCW060326K1FKEA" 0603 1203.41,1325.83 r180 bottom value=26.1k
R31 "CRCW060311K5FKEA" 0603 1102.41,848.83 r180 bottom value=11.5k
R32 "CRCW060310K0FKEA" 0603 1313.41,1357.83 r270 bottom value=10.0k
R33 "CRCW060316K2FKEA" 0603 1102.41,948.83 r180 bottom value=16.2k
R34 "CRCW060322K1FKEA" 0603 1102.41,1048.83 r180 bottom value=22.1k
R35 "CRCW060330K1FKEA" 0603 1102.41,1148.83 r180 bottom value=30.1k
R36 "CRCW060310K0FKEA" 0603 1604.5,1253 r0 bottom value=10.0k
R37 "CRCW060317K4FKEA" 0603 1700,1567 r0 bottom value=17.4k
R38 "CRCW060328K7FKEA" 0603 1700,1668 r0 bottom value=28.7k
R39 "CRCW060310K7FKEA" 0603 1623,1158 r0 bottom value=10.7k
R40 "CRCW060353K6FKEA" 0603 1700,1767 r0 bottom value=53.6k
R41 "CRCW060310K7FKEA" 0603 1697.5,3202 r0 bottom value=10.7k
R42 "CRCW060310K7FKEA" 0603 1700,1468 r0 bottom value=10.7k
SH-J5 "2SN-BK-G" 2SN-BK-G 869,3126 r270 top value=1x2
SH-J6 "2SN-BK-G" 2SN-BK-G 1259,3100 r180 top value=1x2
SH-J7 "2SN-BK-G" 2SN-BK-G 1925,3451 r90 top value=1x2
SH-J8 "2SN-BK-G" 2SN-BK-G 872,2388 r90 top value=1x2
SH-J11 "2SN-BK-G" 2SN-BK-G 1260,2306 r180 top value=1x2
SH-J12 "2SN-BK-G" 2SN-BK-G 1542,3302 r180 top value=1x2
SH-J15 "2SN-BK-G" 2SN-BK-G 873,1026 r90 top value=1x2
SH-J17 "2SN-BK-G" 2SN-BK-G 1947,1715 r90 top value=1x2
SH-J18 "2SN-BK-G" 2SN-BK-G 1264,1147 r180 top value=1x2
SH-J19 "2SN-BK-G" 2SN-BK-G 1547,1570 r180 top value=1x2
TP1 "5010" Keystone5010 588,2717 r180 top
TP2 "5010" Keystone5010 3233,3433 r0 top
TP3 "5012" Keystone5012 250,3550 r180 top
TP4 "5011" Keystone5011 588,1249 r0 top
TP5 "5011" Keystone5011 3233,2881 r0 top
TP6 "5012" Keystone5012 250,2950 r0 top
TP7 "5012" Keystone5012 2344,3416 r0 top
TP8 "5010" Keystone5010 3233,2580 r0 top
TP9 "5011" Keystone5011 3233,2023 r0 top
TP10 "5011" Keystone5011 250,3250 r0 top
TP11 "5010" Keystone5010 3233,1286.32 r180 top
TP12 "5012" Keystone5012 250,900 r0 top
TP13 "5011" Keystone5011 3233.47,824 r0 top
TP14 "5012" Keystone5012 2347,1705 r0 top
TP15 "5011" Keystone5011 250,600 r0 top
TP16 "TESTPOINT" TP_25MIL-SMT 1768,2891 r90 bottom
TP17 "TESTPOINT" TP_25MIL-SMT 1768,2610 r90 bottom
TP18 "TESTPOINT" TP_25MIL-SMT 1769,1208 r90 bottom
TP19 "TESTPOINT" TP_25MIL-SMT 1769,927 r90 bottom
U1 "TPSM5D1806RDB" RDB0051A-MFG 1765,2751 r90 top
U2 "TPSM5D1806RDB" RDB0051A-MFG 1766,1068 r90 top
ZZ1 "This Assembly Note is for PCB labels only" AssemblyNoteLabel 46,6216.58 r0 top
ZZ2 "These assemblies are ESD sensitive, ESD precautions shall be observed." AssemblyNote 46,6107.7 r0 top
ZZ3 "These assemblies must be clean and free from flux and all contaminants. Use of no clean flux is not acceptable." AssemblyNote 46,6011.14 r0 top
ZZ4 "These assemblies must comply with workmanship standards IPC-A-610 Class 2, unless otherwise specified." AssemblyNote 46,5912 r0 top
ZZ5 "Place SH-J5 on J5 pins 1 and 2" AssemblyNote 46,5788 r0 top
ZZ6 "Place SH-J6 on J6 pins 3 and 4" AssemblyNote 46,5682 r0 top
ZZ7 "Place SH-J7 on J7 pins 2 and 3" AssemblyNote 46,5555 r0 top
ZZ8 "Place SH-J8 on J8 pins 1 and 2" AssemblyNote 46,5432 r0 top
ZZ9 "Place SH-J11 on J11 pins 3 and 4" AssemblyNote 46,5308 r0 top
ZZ10 "Place SH-J12 on J12 pins 3 and 4" AssemblyNote 46,5174 r0 top
ZZ11 "Place SH-J15 on J15 pins 1 and 2" AssemblyNote 46,5029 r0 top
ZZ12 "Place SH-J17 on J17 pins 2 and 3" AssemblyNote 46,4909 r0 top
ZZ13 "Place SH-J18 on J18 pins 7 and 8" AssemblyNote 46,4778 r0 top
ZZ14 "Place SH-J19 on J19 pins 3 and 4" AssemblyNote 46,4648 r0 top

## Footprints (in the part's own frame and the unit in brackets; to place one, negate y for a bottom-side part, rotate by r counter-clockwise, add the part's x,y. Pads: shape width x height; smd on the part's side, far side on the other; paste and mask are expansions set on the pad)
2SN-BK-G [mil] "Samtec STEP model"
  round 1 on Mech3: 0(0,0)
  body extent -78,-39 79,39, height 188
0603 [mm] "0603 from SM-752 data"
  rect 1x0.95 smd: 1(-0.8,0) 2(0.8,0)
  silkscreen extent -1.52,-0.69 1.52,0.69, body extent -0.87,-0.47 0.87,0.47, height 1
1206_180 [mm] "1206_180"
  rect 1.1x1.6 smd: 1(-1.7,0) 2(1.7,0)
  silkscreen extent -0.9,-1 0.9,1, body extent -1.75,-0.95 1.75,0.95, height 1.8
1206_190 [mm] "1206_190"
  rect 1.1x1.6 smd: 1(-1.7,0) 2(1.7,0)
  silkscreen extent -0.9,-1 0.9,1, body extent -1.75,-0.95 1.75,0.95, height 1.9
7343-40 [mm] "Molded, 2-Leads, Body 7.3x4.3mm, Height 4mm"
  rect 2.4x2.9 smd: 1(-3.05,0) 2(3.05,0)
  silkscreen extent -3.8,-2.25 3.8,2.25, body extent -3.8,-2.25 3.8,2.25, height 4.01
AssemblyNote [mil] "Assembly Note"
AssemblyNoteLabel [mil] "Assembly Note for PCB Labels"
CE_Mark_5mm [mil] "Minimum text height for CE Mark"
  silkscreen extent -138,-98 138,98
CONN_PEC03SAAN [mm] "SULLINS"
  rect 1.5x1.5 hole 1.016: 1(-2.54,0)
  round 1.5 hole 1.016: 2(0,0) 3(2.54,0)
  silkscreen extent -4.72,-1.27 3.81,1.27, body extent -3.84,-1.3 3.84,1.3, height 8.38
CONN_PEC04DAAN [mm] "SULLINS"
  rect 1.65x1.65 hole 1.016 mask+0: 1(-3.81,-1.27)
  round 1.65 hole 1.016 mask+0: 2(-3.81,1.27) 3(-1.27,-1.27) 4(-1.27,1.27) 5(1.27,-1.27) 6(1.27,1.27) 7(3.81,-1.27) 8(3.81,1.27)
  silkscreen extent -6.18,-2.6 5.08,2.54, body extent -5.08,-2.54 5.08,2.54, height 8.38
CONN_PEC05DAAN [mm] "SULLINS"
  rect 1.65x1.65 hole 1.016 mask+0: 1(-5.08,-1.27)
  round 1.65 hole 1.016 mask+0: 2(-5.08,1.27) 3(-2.54,-1.27) 4(-2.54,1.27) 5(0,-1.27) 6(0,1.27) 7(2.54,-1.27) 8(2.54,1.27) 9(5.08,-1.27) 10(5.08,1.27)
  silkscreen extent -7.45,-2.6 6.35,2.54, body extent -6.35,-2.54 6.35,2.54, height 8.38
FCC_disclaimer [mil]
Fiducial10-30 [mm]
  round 1 smd mask+1: 1(0,0)
  Top Layer keep-out circle w1.678: c0,0 r0.75
Keystone5010 [mil] "Keystone Multipurpose loops"
  round 87 hole 63: 1(0,0)
  silkscreen extent -70,-70 70,70, body extent -63,-63 63,62, height 319
Keystone5011 [mil] "Keystone Multipurpose loops"
  round 87 hole 63: 1(0,0)
  silkscreen extent -70,-70 70,70, body extent -63,-63 63,62, height 319
Keystone5012 [mil] "Keystone Multipurpose loops"
  round 87 hole 63: 1(0,0)
  silkscreen extent -70,-70 70,70, body extent -63,-63 63,62, height 319
Mill-max_310-43-102-41-001000 [mm] "Mill-max"
  rect 1.35x1.35 hole 0.75: 1(-1.27,0)
  round 1.35 hole 0.75: 2(1.27,0)
  silkscreen extent -3.22,-1.3 2.6,1.3, body extent -2.55,-1.27 2.55,1.27, height 4.22
Net-Tie_10mil#1 [mil] "10mil net tie, no solder mask opening, no solder paste"
  rect 10x10 smd paste-5 mask-5: 1(-10,0) 2(10,0)
  Top Layer region: -6,5 6,5 6,-5 -6,-5
Net-Tie_10mil#2 [mil] "10mil net tie, no solder mask opening, no solder paste"
  rect 10x10 on Mid3 paste-5 mask-5: 1(-10,0) 2(10,0)
  Mid-Layer 3 region: -6,5 6,5 6,-5 -6,-5
On-Shore_ED120_2DS [mm] "ONSHORE"
  rrect5% 2x2 hole 1.25: 1(-2.54,0)
  round 2 hole 1.25: 2(2.54,0)
  silkscreen extent -5.6,-4 5.12,5, body extent -5.78,-4 5.08,5, height 13
RDB0051A-MFG [mm]
  round 0.256 smd paste-1000 mask+0: 1(-2.267,3.562) 15(-2.267,-3.562)
  rrect40% 0.7x0.25 smd paste+0 mask+0: 2(-2.6,3) 3(-2.6,2.5) 7(-2.6,0.5) 8(-2.6,0) 9(-2.6,-0.5) 13(-2.6,-2.5) 14(-2.6,-3) 25(2.6,-3) 26(2.6,-2.5) 30(2.6,-0.5) 31(2.6,0) 32(2.6,0.5) 36(2.6,2.5) 37(2.6,3)
  rrect40% 1.2x0.25 smd paste+0 mask+0: 4(-2.35,2) 5(-2.35,1.5) 6(-2.35,1) 10(-2.35,-1) 11(-2.35,-1.5) 12(-2.35,-2) 27(2.35,-2) 28(2.35,-1.5) 29(2.35,-1) 33(2.35,1) 34(2.35,1.5) 35(2.35,2)
  rrect40% 0.25x0.7 smd paste+0 mask+0: 16(-1.75,-3.85) 17(-1.25,-3.85) 18(-0.75,-3.85) 19(-0.25,-3.85) 20(0.25,-3.85) 21(0.75,-3.85) 22(1.25,-3.85) 23(1.75,-3.85) 39(1.75,3.85) 40(1.25,3.85) 41(0.75,3.85) 42(0.25,3.85) 43(-0.25,3.85) 44(-0.75,3.85) 45(-1.25,3.85) 46(-1.75,3.85)
  round 0.324 smd paste-1000 mask+0: 24(2.312,-3.562) 38(2.312,3.562)
  rrect4% 2.5x5 smd paste-1000 mask+0: 47-48-49-50-51(0,0)
  Top Layer region: 2.955,3.624 2.955,3.425 2.951,3.406 2.94,3.389 2.923,3.379 2.904,3.375 2.904,3.375 2.175,3.375 2.156,3.379 2.139,3.39 2.129,3.407 2.125,3.426 2.125,3.426 2.125,3.825 2.129,3.844 2.14,3.861 2.157,3.871 2.176,3.875 2.176,3.875 2.375,3.875 2.394,3.871 2.411,3.86 2.421,3.843 2.425,3.824 2.425,3.824 2.425,3.726 2.429,3.707 2.439,3.69 2.456,3.679 2.475,3.675 2.475,3.675 2.9,3.675 2.921,3.673 2.939,3.662 2.951,3.645 2.955,3.624
  Top Layer region: 2.955,-3.624 2.955,-3.425 2.951,-3.406 2.94,-3.389 2.923,-3.379 2.904,-3.375 2.904,-3.375 2.175,-3.375 2.156,-3.379 2.139,-3.39 2.129,-3.407 2.125,-3.426 2.125,-3.426 2.125,-3.825 2.129,-3.844 2.14,-3.861 2.157,-3.871 2.176,-3.875 2.176,-3.875 2.375,-3.875 2.394,-3.871 2.411,-3.86 2.421,-3.843 2.425,-3.824 2.425,-3.824 2.425,-3.726 2.429,-3.707 2.439,-3.69 2.456,-3.679 2.475,-3.675 2.475,-3.675 2.9,-3.675 2.921,-3.673 2.939,-3.662 2.951,-3.645 2.955,-3.624
  Top Layer region: -2.955,3.624 -2.955,3.425 -2.951,3.406 -2.94,3.389 -2.923,3.379 -2.904,3.375 -2.904,3.375 -2.175,3.375 -2.156,3.379 -2.139,3.39 -2.129,3.407 -2.125,3.426 -2.125,3.426 -2.125,3.825 -2.129,3.844 -2.14,3.861 -2.157,3.871 -2.176,3.875 -2.176,3.875 -2.375,3.875 -2.394,3.871 -2.411,3.86 -2.421,3.843 -2.425,3.824 -2.425,3.824 -2.425,3.726 -2.429,3.707 -2.439,3.69 -2.456,3.679 -2.475,3.675 -2.475,3.675 -2.9,3.675 -2.921,3.673 -2.939,3.662 -2.951,3.645 -2.955,3.624
  Top Layer region: -2.955,-3.624 -2.955,-3.425 -2.951,-3.406 -2.94,-3.389 -2.923,-3.379 -2.904,-3.375 -2.904,-3.375 -2.175,-3.375 -2.156,-3.379 -2.139,-3.39 -2.129,-3.407 -2.125,-3.426 -2.125,-3.426 -2.125,-3.825 -2.129,-3.844 -2.14,-3.861 -2.157,-3.871 -2.176,-3.875 -2.176,-3.875 -2.375,-3.875 -2.394,-3.871 -2.411,-3.86 -2.421,-3.843 -2.425,-3.824 -2.425,-3.824 -2.425,-3.726 -2.429,-3.707 -2.439,-3.69 -2.456,-3.679 -2.475,-3.675 -2.475,-3.675 -2.9,-3.675 -2.921,-3.673 -2.939,-3.662 -2.951,-3.645 -2.955,-3.624
  silkscreen extent -3.65,-4.3 2.8,4.3, body extent -3.06,-4.3 3.06,4.3, height 0.25
SM_RADIAL_G [mm] "10 x 10.2mm:  Panasonic G"
  rect 4.1x2 smd: 1(-4.35,0) 2(4.35,0)
  silkscreen extent -5.35,-5.35 5.35,5.35, body extent -5.25,-5.25 5.25,5.25, height 10.5
TP_25MIL-SMT [mil]
  round 25 smd mask-2.5: 1(0,0)
WEEE_Minimum [mil] "WEEElie bin"
  silkscreen extent -95,-172 99,104

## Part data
C1: library part CMP-0010657-1, "CAP, AL, 330 uF, 25 V, +/- 20%, 0.15 ohm, SMD", Cap_Case=G, Manufacturer=Panasonic, Supplier Part Number 1=PCE4007CT-ND, Tolerance_%=20%, Value1="0.15 ohm", Value2=25V, ValueDisplayed=330uF
C2 C3 C4 C5 C25 C26 C27 C28: library part CMP-0008656-2, "CAP, CERM, 47 uF, 25 V, +/- 20%, X5R, 1206_190", Cap_Case=1206, Manufacturer=TDK, Supplier Part Number 1=445-8047-1-ND, TempCo=X5R, Tolerance_%=20%, Value1=Unknown, Value2=25V, ValueDisplayed=47uF
C6 C23 C29 C47: library part CMP-0064986-2, "CAP, Tantalum Polymer, 330 uF, 10 V,+/- 20%, 0.035 ohm, 7343-40 SMD", Cap_Case=7343-40, Manufacturer=Kemet, Supplier Part Number 1=399-10363-1-ND, Tolerance_%=20%, Value1="0.035 ohm", Value2=10V, ValueDisplayed=330uF
C7 C8 C9 C10 C11 C12 C13 C14 C15 C16 C17 C18 C19 C20 C21 C22 C30 C31 C32 C33 C34 C35 C36 C37 C39 C40 C41 C42 C43 C44 C45 C46: library part CMP-0008934-2, "CAP, CERM, 100 uF, 6.3 V, +/- 20%, X5R, 1206", Cap_Case=1206, Manufacturer=MuRata, Supplier Part Number 1=490-4539-1-ND, TempCo=X5R, Tolerance_%=20%, Value1="0.003 ohm", Value2=6.3V, ValueDisplayed=100uF
C24 C48: library part CMP-0007026-4, "CAP, CERM, 2.2 uF, 16 V, +/- 10%, X6S, 0603", Cap_Case=0603, Manufacturer=TDK, Supplier Part Number 1=445-7438-1-ND, TempCo=X6S, Tolerance_%=10%, Value1="0.007674 ohm", Value2=16V, ValueDisplayed=2.2uF
C38: library part CMP-0007049-4, "CAP, CERM, 0.047 uF, 50 V, +/- 10%, X7R, 0603", Cap_Case=0603, Manufacturer=TDK, Supplier Part Number 1=445-1313-1-ND, TempCo=X7R, Tolerance_%=10%, Value1="0.049007 ohm", Value2=50V, ValueDisplayed=0.047uF
FID1 FID2 FID3 FID4 FID5 FID6: library part CMP-0077181-1, "Fiducial mark.  There is nothing to buy or mount.", Manufacturer=N/A
J1 J3 J4 J10 J13 J16: library part CMP-0074910-1, "Terminal Block, 5.08 mm, 2x1, Brass, TH", Color=Blue, Current_A=15A, Manufacturer="On-Shore Technology", Supplier Part Number 1=ED1609-ND, Voltage_V=300V
J2 J9 J14: library part CMP-0055017-1, "Socket Strip, 2x1, 100mil, Black, Tin, TH", Manufacturer=Mill-Max, Supplier Part Number 1=ED6202-ND
J5 J7 J8 J15 J17: library part CMP-0002338-1, "Header, 100mil, 3x1, Tin, TH", Color=Black, Current_A=3A, Manufacturer="Sullins Connector Solutions", Supplier Part Number 1=S1012E-03-ND, Voltage_V=1.8kV
J6 J11 J18: library part CMP-0054550-2, "Header, 100mil, 5x2, Tin, TH", Color=Black, Current_A=3A, Manufacturer="Sullins Connector Solutions", Supplier Part Number 1=S2012E-05-ND, Voltage_V=1.8kV
J12 J19: library part CMP-0054542-2, "Header, 100mil, 4x2, Tin, TH", Color=Black, Current_A=3A, Manufacturer="Sullins Connector Solutions", Supplier Part Number 1=S2012E-04-ND, Voltage_V=1.8kV
Logo1: library part CMP-0074844-1
Logo3: library part CMP-0074847-1, "FCC_disclaimer"
Logo4: library part CMP-0074769-1
NT1 NT2 NT3: library part CMP-0078142-3, "Single point connection between nets.", Manufacturer=N/A
R1 R7 R8 R15 R18 R20 R26 R32 R36: library part CMP-0021998-4, "RES, 10.0 k, 1%, 0.1 W, AEC-Q200 Grade 0, 0603", Manufacturer=Vishay-Dale, Power_W=100mW, Supplier Part Number 1=541-10.0KHCT-ND, TempCo="100 ppm/C", Tolerance_%=1%, Value2=0.1W, Value_Code=10k0, ValueDisplayed=10.0k
R2 R13 R27: library part CMP-0025697-4, "RES, 0, 5%, 0.1 W, AEC-Q200 Grade 0, 0603", Manufacturer=Vishay-Dale, Power_W=100mW, Supplier Part Number 1=541-0.0GCT-ND, TempCo="200 ppm/C", Tolerance_%=5%, Value2=0.1W, Value_Code=0000, ValueDisplayed=0
R3 R11 R28: library part CMP-0021990-4, "RES, 100 k, 1%, 0.1 W, AEC-Q200 Grade 0, 0603", Manufacturer=Vishay-Dale, Power_W=100mW, Supplier Part Number 1=541-100KHCT-ND, TempCo="100 ppm/C", Tolerance_%=1%, Value2=0.1W, Value_Code=100k
R4 R14 R29: library part CMP-0022347-4, "RES, 34.8 k, 1%, 0.1 W, AEC-Q200 Grade 0, 0603", Manufacturer=Vishay-Dale, Power_W=100mW, Supplier Part Number 1=541-34.8KHCT-ND, TempCo="100 ppm/C", Tolerance_%=1%, Value2=0.1W, Value_Code=34k8, ValueDisplayed=34.8k
R5: library part CMP-0022499-4, "RES, 56.2 k, 1%, 0.1 W, AEC-Q200 Grade 0, 0603", Manufacturer=Vishay-Dale, Power_W=100mW, Supplier Part Number 1=541-56.2KHCT-ND, TempCo="100 ppm/C", Tolerance_%=1%, Value2=0.1W, Value_Code=56k2, ValueDisplayed=56.2k
R6: library part CMP-0022563-4, "RES, 6.81 k, 1%, 0.1 W, AEC-Q200 Grade 0, 0603", Manufacturer=Vishay-Dale, Power_W=100mW, Supplier Part Number 1=541-6.81KHCT-ND, TempCo="100 ppm/C", Tolerance_%=1%, Value2=0.1W, Value_Code=6k81, ValueDisplayed=6.81k
R9: library part CMP-0022030-4, "RES, 12.1 k, 1%, 0.1 W, AEC-Q200 Grade 0, 0603", Manufacturer=Vishay-Dale, Power_W=100mW, Supplier Part Number 1=541-12.1KHCT-ND, TempCo="100 ppm/C", Tolerance_%=1%, Value2=0.1W, Value_Code=12k1, ValueDisplayed=12.1k
R10: library part CMP-0022098-4, "RES, 18.7 k, 1%, 0.1 W, AEC-Q200 Grade 0, 0603", Manufacturer=Vishay-Dale, Power_W=100mW, Supplier Part Number 1=541-18.7KHCT-ND, TempCo="100 ppm/C", Tolerance_%=1%, Value2=0.1W, Value_Code=18k7, ValueDisplayed=18.7k
R12: library part CMP-0022443-4, "RES, 48.7 k, 1%, 0.1 W, AEC-Q200 Grade 0, 0603", Manufacturer=Vishay-Dale, Power_W=100mW, Supplier Part Number 1=541-48.7KHCT-ND, TempCo="100 ppm/C", Tolerance_%=1%, Value2=0.1W, Value_Code=48k7, ValueDisplayed=48.7k
R16 R25: library part CMP-0022410-4, "RES, 40.2 k, 1%, 0.1 W, AEC-Q200 Grade 0, 0603", Manufacturer=Vishay-Dale, Power_W=100mW, Supplier Part Number 1=541-40.2KHCT-ND, TempCo="100 ppm/C", Tolerance_%=1%, Value2=0.1W, Value_Code=40k2, ValueDisplayed=40.2k
R17 R22 R37: library part CMP-0022089-4, "RES, 17.4 k, 1%, 0.1 W, AEC-Q200 Grade 0, 0603", Manufacturer=Vishay-Dale, Power_W=100mW, Supplier Part Number 1=541-17.4KHCT-ND, TempCo="100 ppm/C", Tolerance_%=1%, Value2=0.1W, Value_Code=17k4, ValueDisplayed=17.4k
R19 R38: library part CMP-0022261-4, "RES, 28.7 k, 1%, 0.1 W, AEC-Q200 Grade 0, 0603", Manufacturer=Vishay-Dale, Power_W=100mW, Supplier Part Number 1=541-28.7KHCT-ND, TempCo="100 ppm/C", Tolerance_%=1%, Value2=0.1W, Value_Code=28k7, ValueDisplayed=28.7k
R21: library part CMP-0022067-4, "RES, 15.4 k, 1%, 0.1 W, AEC-Q200 Grade 0, 0603", Manufacturer=Vishay-Dale, Power_W=100mW, Supplier Part Number 1=541-15.4KHCT-ND, TempCo="100 ppm/C", Tolerance_%=1%, Value2=0.1W, Value_Code=15k4, ValueDisplayed=15.4k
R23 R40: library part CMP-0022490-4, "RES, 53.6 k, 1%, 0.1 W, AEC-Q200 Grade 0, 0603", Manufacturer=Vishay-Dale, Power_W=100mW, Supplier Part Number 1=541-53.6KHCT-ND, TempCo="100 ppm/C", Tolerance_%=1%, Value2=0.1W, Value_Code=53k6, ValueDisplayed=53.6k
R24: library part CMP-0022213-4, "RES, 21.5 k, 1%, 0.1 W, AEC-Q200 Grade 0, 0603", Manufacturer=Vishay-Dale, Power_W=100mW, Supplier Part Number 1=541-21.5KHCT-ND, TempCo="100 ppm/C", Tolerance_%=1%, Value2=0.1W, Value_Code=21k5, ValueDisplayed=21.5k
R30: library part CMP-0022248-4, "RES, 26.1 k, 1%, 0.1 W, AEC-Q200 Grade 0, 0603", Manufacturer=Vishay-Dale, Power_W=100mW, Supplier Part Number 1=541-26.1KHCT-ND, TempCo="100 ppm/C", Tolerance_%=1%, Value2=0.1W, Value_Code=26k1, ValueDisplayed=26.1k
R31: library part CMP-0022018-4, "RES, 11.5 k, 1%, 0.1 W, AEC-Q200 Grade 0, 0603", Manufacturer=Vishay-Dale, Power_W=100mW, Supplier Part Number 1=541-11.5KHCT-ND, TempCo="100 ppm/C", Tolerance_%=1%, Value2=0.1W, Value_Code=11k5, ValueDisplayed=11.5k
R33: library part CMP-0022079-4, "RES, 16.2 k, 1%, 0.1 W, AEC-Q200 Grade 0, 0603", Manufacturer=Vishay-Dale, Power_W=100mW, Supplier Part Number 1=541-16.2KHCT-ND, TempCo="100 ppm/C", Tolerance_%=1%, Value2=0.1W, Value_Code=16k2, ValueDisplayed=16.2k
R34: library part CMP-0022220-4, "RES, 22.1 k, 1%, 0.1 W, AEC-Q200 Grade 0, 0603", Manufacturer=Vishay-Dale, Power_W=100mW, Supplier Part Number 1=541-22.1KHCT-ND, TempCo="100 ppm/C", Tolerance_%=1%, Value2=0.1W, Value_Code=22k1, ValueDisplayed=22.1k
R35: library part CMP-0022324-4, "RES, 30.1 k, 1%, 0.1 W, AEC-Q200 Grade 0, 0603", Manufacturer=Vishay-Dale, Power_W=100mW, Supplier Part Number 1=541-30.1KHCT-ND, TempCo="100 ppm/C", Tolerance_%=1%, Value2=0.1W, Value_Code=30k1, ValueDisplayed=30.1k
R39 R41 R42: library part CMP-0022001-4, "RES, 10.7 k, 1%, 0.1 W, AEC-Q200 Grade 0, 0603", Manufacturer=Vishay-Dale, Power_W=100mW, Supplier Part Number 1=541-10.7KHCT-ND, TempCo="100 ppm/C", Tolerance_%=1%, Value2=0.1W, Value_Code=10k7, ValueDisplayed=10.7k
SH-J5 SH-J6 SH-J7 SH-J8 SH-J11 SH-J12 SH-J15 SH-J17 SH-J18 SH-J19: library part CMP-0003641-1, "Shunt, 2mm, Gold plated, Black", Manufacturer=Samtec, Supplier Part Number 1=SAM8748-ND
TP1 TP2 TP8 TP11: library part CMP-0055147-1, "Test Point, Multipurpose, Red, TH", Color=Red, Manufacturer=Keystone, Supplier Part Number 1=36-5010-ND
TP3 TP6 TP7 TP12 TP14: library part CMP-0055149-1, "Test Point, Multipurpose, White, TH", Color=White, Manufacturer=Keystone, Supplier Part Number 1=36-5012-ND
TP4 TP5 TP9 TP10 TP13 TP15: library part CMP-0055148-1, "Test Point, Multipurpose, Black, TH", Color=Black, Manufacturer=Keystone, Supplier Part Number 1=36-5011-ND
TP16 TP17 TP18 TP19: library part CMP-0078143-3, "TEST POINT.  No entry in BOM.", Manufacturer=N/A
U1 U2: library part CMP-0088389-1, "4.5-V to 18-V Input, Dual 6-A Output Power Module with Current Sharing", Manufacturer="Texas Instruments", Max Supply Voltage=18V, Min Supply Voltage=4.5V, Nominal Supply Current=2500uA, Operating Temperature Range="-40°C to +150°C", Output Voltage=0.5-5.5V, Switching Frequency=500/1000/1500/2250kHz
ZZ1: library part CMP-0003616-3
ZZ2: library part CMP-0077236-1
ZZ3: library part CMP-0077237-1
ZZ4: library part CMP-0077238-1
ZZ5 ZZ6 ZZ7 ZZ8 ZZ9 ZZ10 ZZ11 ZZ12 ZZ13 ZZ14: library part CMP-0003615-1, "This Assembly Note will show in the PcbDoc and associated outputs"

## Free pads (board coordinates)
  round 120 hole 126 unplated: 2(150,150) 2(150,3850) 2(3850,143.4) 2(3850,3850)

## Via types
v1: diameter 25, hole 7.8, Top Layer to Bottom Layer, 137 vias
v2: diameter 22, hole 7.8, Top Layer to Bottom Layer, 29 vias
v3: diameter 19.68, hole 7.87, Top Layer to Bottom Layer, 24 vias

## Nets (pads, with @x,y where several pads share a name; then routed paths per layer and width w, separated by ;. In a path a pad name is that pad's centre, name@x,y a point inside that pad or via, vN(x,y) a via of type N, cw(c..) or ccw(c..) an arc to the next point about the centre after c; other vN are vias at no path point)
0.8VO1: J6.2 R6.1 | length 78.5
  Bottom Layer w15: R6.1@1131.5,3001 J6.2@1210,3001
0.9VO2: J11.2 R18.1 | length 77.9
  Bottom Layer w15: R18.1@1131.5,2210 J11.2@1209.42,2210
0.9VO3: J18.2 R31.1 | length 77.9
  Bottom Layer w15: R31.1@1133.91,848.83 J18.2@1211.83,848.83
1.0MHz: J12.3 R17.1 | length 74
  Bottom Layer w15: J12.3@1593,3302 R17.1@1667,3302
1.0MHz.: J19.3 R37.1 | length 74.9
  Bottom Layer w10: R37.1@1667.5,1568 R37.1@1668.5,1567
  Bottom Layer w15: J19.3@1594,1568 R37.1@1667.5,1568
1.0VO1: J6.4 R9.1 | length 78.5
  Bottom Layer w15: R9.1@1131.5,3101 J6.4@1210,3101
1.0VO3: J18.4 R33.1 | length 64
  Bottom Layer w15: R33.1@1133.91,948.83 J18.4@1197.17,948.83 ; J18.4@1211.5,949.5 J18.4@1212,949
1.1VO2: J11.4 R22.1 | length 77.9
  Bottom Layer w15: R22.1@1131.5,2310 J11.4@1209.42,2310
1.1VO3: J18.6 R34.1 | length 77.9
  Bottom Layer w15: R34.1@1133.91,1048.83 J18.6@1211.83,1048.83
1.2VO1: J6.6 R10.1 | length 78.5
  Bottom Layer w15: R10.1@1131.5,3201 J6.6@1210,3201
1.2VO2: J11.6 R24.1 | length 77.9
  Bottom Layer w15: R24.1@1131.5,2410 J11.6@1209.42,2410
1.2VO3: J18.8 R35.1 | length 77.9
  Bottom Layer w15: R35.1@1133.91,1148.83 J18.8@1211.83,1148.83
1.5MHz: J12.5 R19.1 | length 73.5
  Bottom Layer w15: J12.5@1593,3402 R19.1@1666.5,3402
1.5MHz.: J19.5 R38.1 | length 74.5
  Bottom Layer w15: J19.5@1594,1668 R38.1@1668.5,1668
1.5VO2: J11.8 R25.1 | length 77.9
  Bottom Layer w15: R25.1@1131.5,2510 J11.8@1209.42,2510
1.8VO1: J6.8 R12.1 | length 77.9
  Bottom Layer w15: R12.1@1131.5,3301 J6.8@1208,3301 ; J6.8@1209,3300 J6.8@1210,3301
1.8VO3: J18.10
2.0MHz: J12.7 R23.1 | length 73
  Bottom Layer w15: J12.7@1593,3502 R23.1@1666,3502
2.0MHz.: J19.7 R40.1 | length 74.9
  Bottom Layer w10: R40.1@1667.5,1768 R40.1@1668.5,1767
  Bottom Layer w15: J19.7@1594,1768 R40.1@1667.5,1768
2.5VO2: J11.10
3.3VO1: J6.10
500kHz: J12.1 R41.1 | length 73
  Bottom Layer w10: J12.1@1593,3202 R41.1@1666,3202
500kHz.: J19.1 R42.1 | length 74.9
  Bottom Layer w15: J19.1@1594,1469 1595,1468 R42.1@1668.5,1468
AGND1: C24.2 J12.2 J12.4 J12.6 J12.8 NT1.1 R8.1 R20.1 R21.1 TP5.1 TP9.1 TP10.1 U1.39 U1.41 U1.42 U1.43 | length 4906.3
  Top Layer w9.8: v2(1551.58,2855.42) 1587.1,2819.9 U1.39@1613.43,2819.9
  Mid-Layer 3 w10: v1(1416,3104) 3010,3104 TP5.1@3233,2881 ; v1(1475,2023) TP9.1@3233,2023
  Mid-Layer 4 w10: TP10.1@250,3250 517,2983 827,2983 969,2841 v1(1223,2841)
  Bottom Layer w10: 1644,2751 NT1.1@1664,2751
  other v2: 1562,2751 1585,2751
AGND2: C38.2 C48.2 J19.2 J19.4 J19.6 J19.8 NT3.1 R32.1 R39.1 TP15.1 U2.42 U2.43 | length 1155.4
  Mid-Layer 4 w10: TP15.1@250,600 v1(1341,600)
  Bottom Layer w10: v2@1599.58,1067 NT3.1@1664,1067
  other v2: 1567,1063.51 1590,1064
BP5-1: C24.1 J7.3 R1.2 R7.2 U1.44 | length 1167.1
  Top Layer w9.8: v2@1555,2717 1559.47,2721.47 U1.44@1613.43,2721.47
  Mid-Layer 4 w10: v2(1558.91,2715.09) 1549.91,2715.09 1489.63,2775.37 1489.63,2971.63 1774,3256 1774,3352 J7.3@1924,3502
  Bottom Layer w9.8: v2(1558.91,2715.09) 1561.07,2712.93 R1.2@1664.07,2712.93
BP5-3: C48.1 J17.3 R26.2 U2.44 | length 1171.4
  Top Layer w10: C48.1@1530,1000.5 1550.93,1000.5 1588.9,1038.47 U2.44@1614.43,1038.47
  Mid-Layer 4 w10: v2(1559,1008) 1484,1083 1484,1238 1682,1436 1682,1547 1899,1764 J17.3@1947,1764
  Bottom Layer w9.8: v2(1559,1008) 1576.5,990.5 R26.2@1576.5,951
EN1: J5.2 R3.1 R4.2 U1.1 | length 1485
  Top Layer w9.8: v2(1565,2561) 1565,2613 1613.73,2661.73 U1.1@1624.74,2661.73
  Mid-Layer 3 w10: J5.2@870,3178 938.44,3178 983,3133.44 983,2823 1063,2743 1467,2743 1565,2645 v2(1565,2561)
  Bottom Layer w15: R3.1@700,3177.09 778,3177.09 R4.2@779,3178.09 J5.2@867.5,3178.09 ; J5.2@867.5,3180.5 J5.2@870,3178
EN2: J8.2 R11.1 R14.2 U1.46 | length 1121.5
  Top Layer w9.8: v2(1445,2590) 1511,2590 1603.1,2682.1 U1.46@1613.43,2682.1
  Mid-Layer 3 w10: J8.2@870,2441 930.19,2441 978.44,2489.25 978.44,2605.83 1050.61,2678 1357.81,2678 1445,2590.81 v2(1445,2590)
  Bottom Layer w15: R11.1@721,2440.5 R14.2@789,2440.5 ; R14.2@801.5,2441 J8.2@870,2441
EN3: J15.2 R28.1 R29.2 U2.1 | length 1346.7
  Top Layer w9.8: v2(1545,909) 1614.73,978.73 U2.1@1625.74,978.73
  Mid-Layer 3 w10: J15.2@872,1077 950,1077 1002,1025 1002,872 1183,691 1476.81,691 1545,759.19 v2(1545,909)
  Bottom Layer w15: R28.1@723.41,1079.33 R29.2@791.41,1079.33 ; R29.2@803.92,1079.83 J15.2@872.41,1079.83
